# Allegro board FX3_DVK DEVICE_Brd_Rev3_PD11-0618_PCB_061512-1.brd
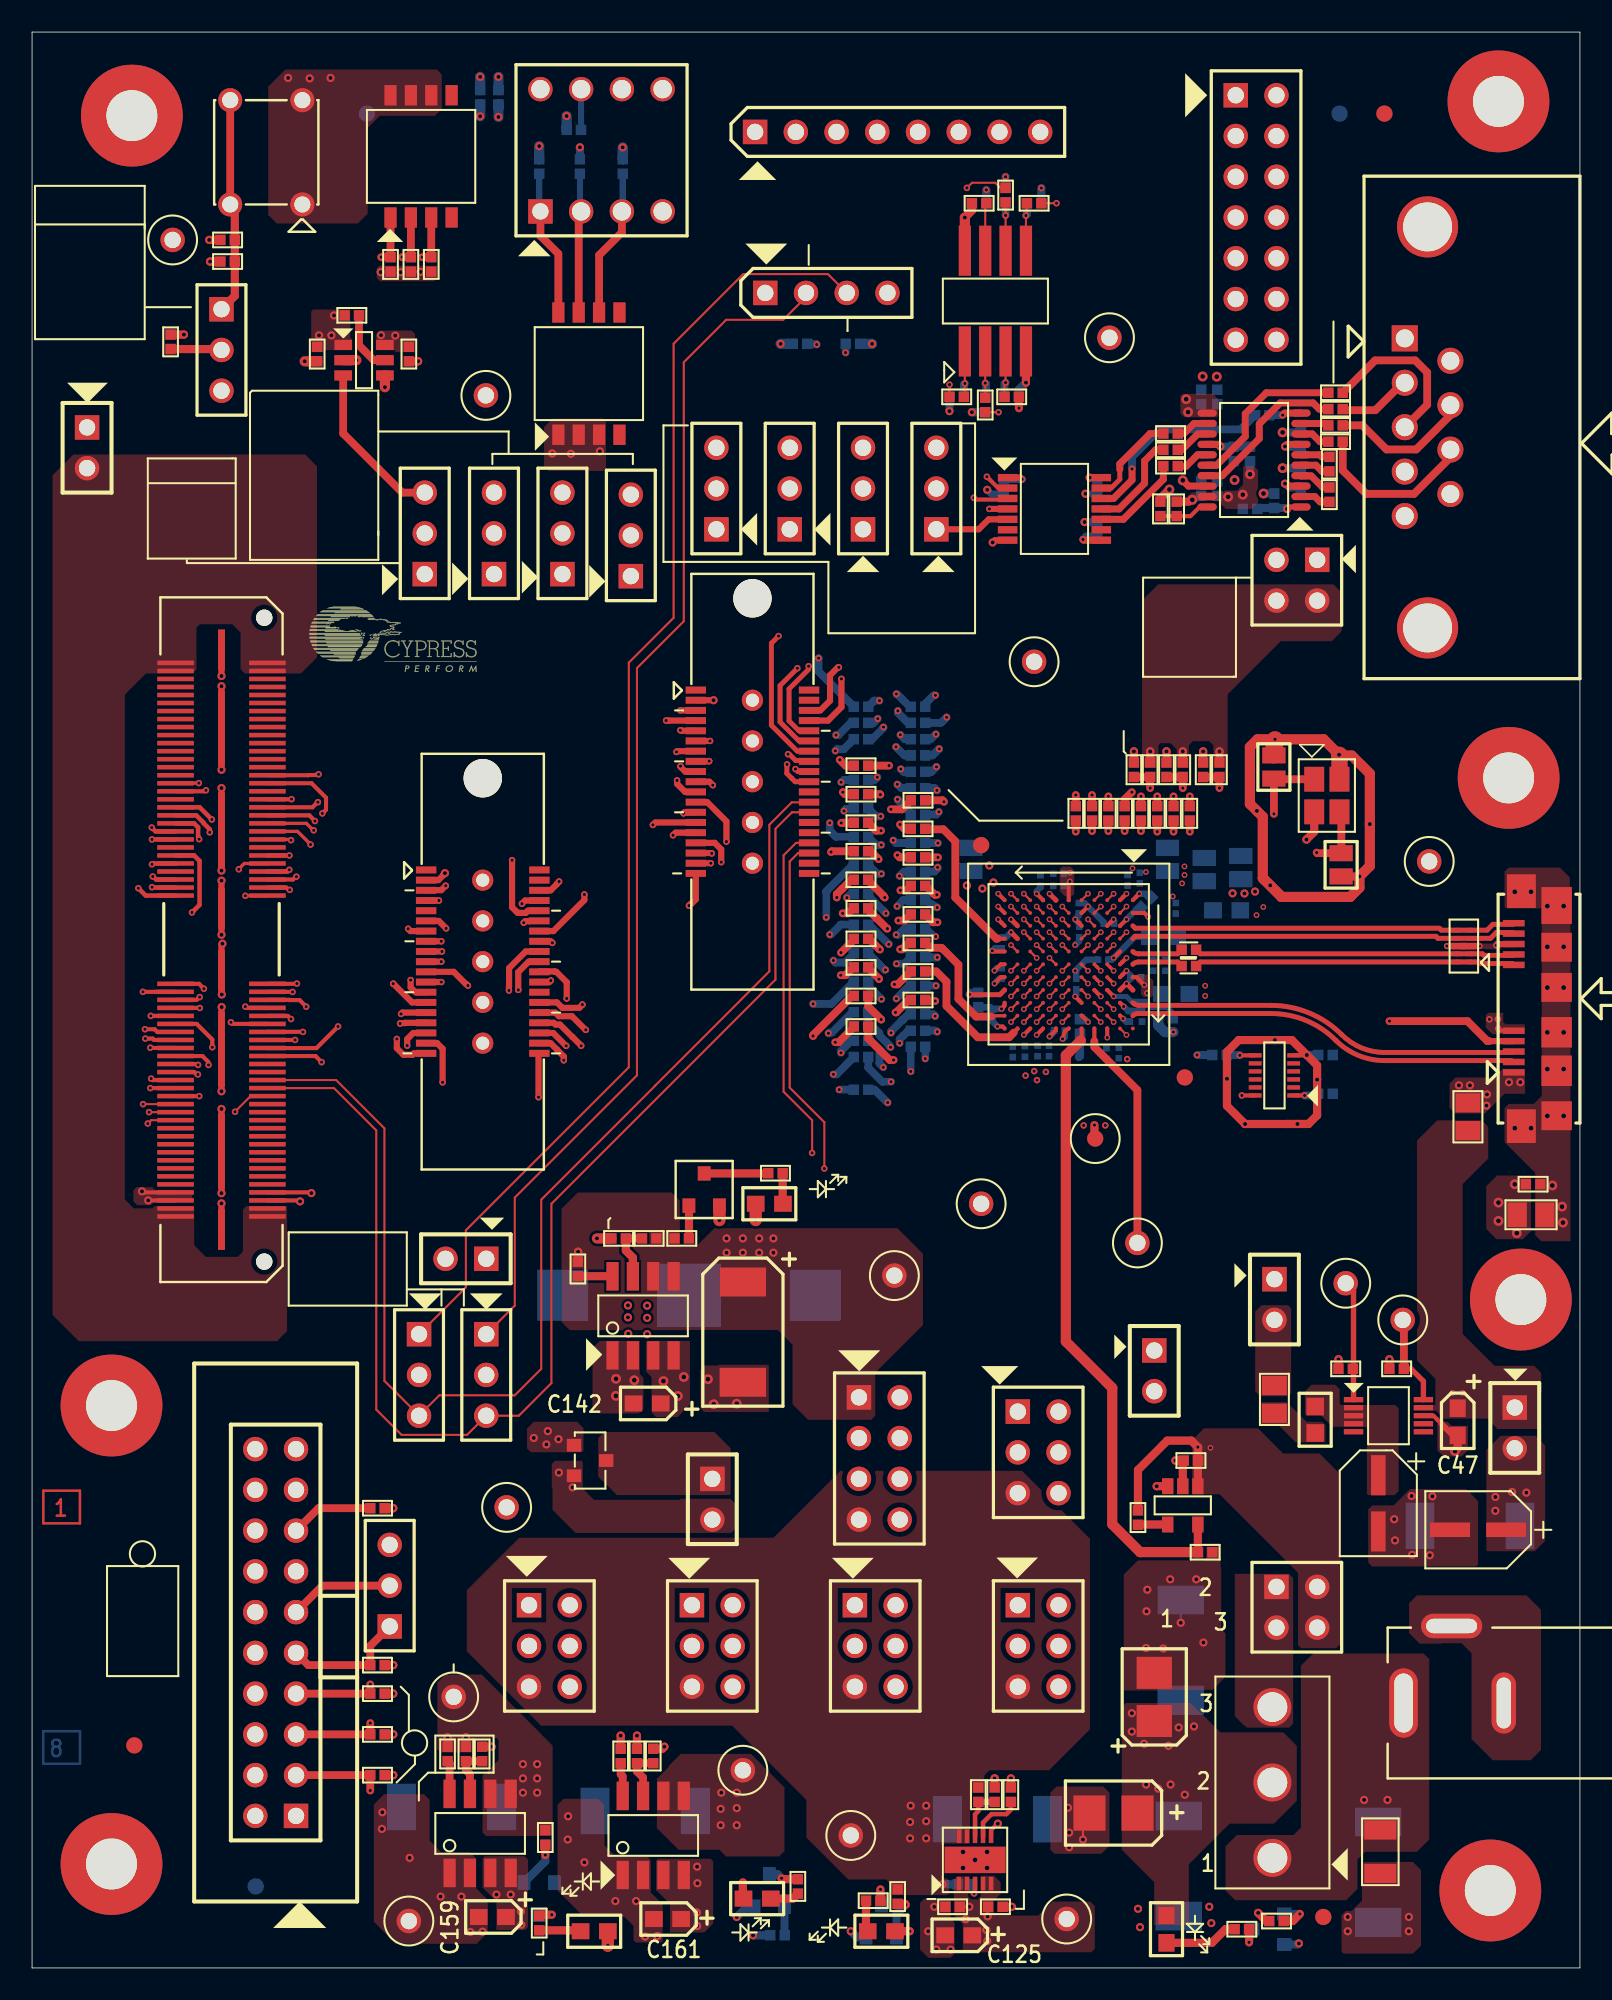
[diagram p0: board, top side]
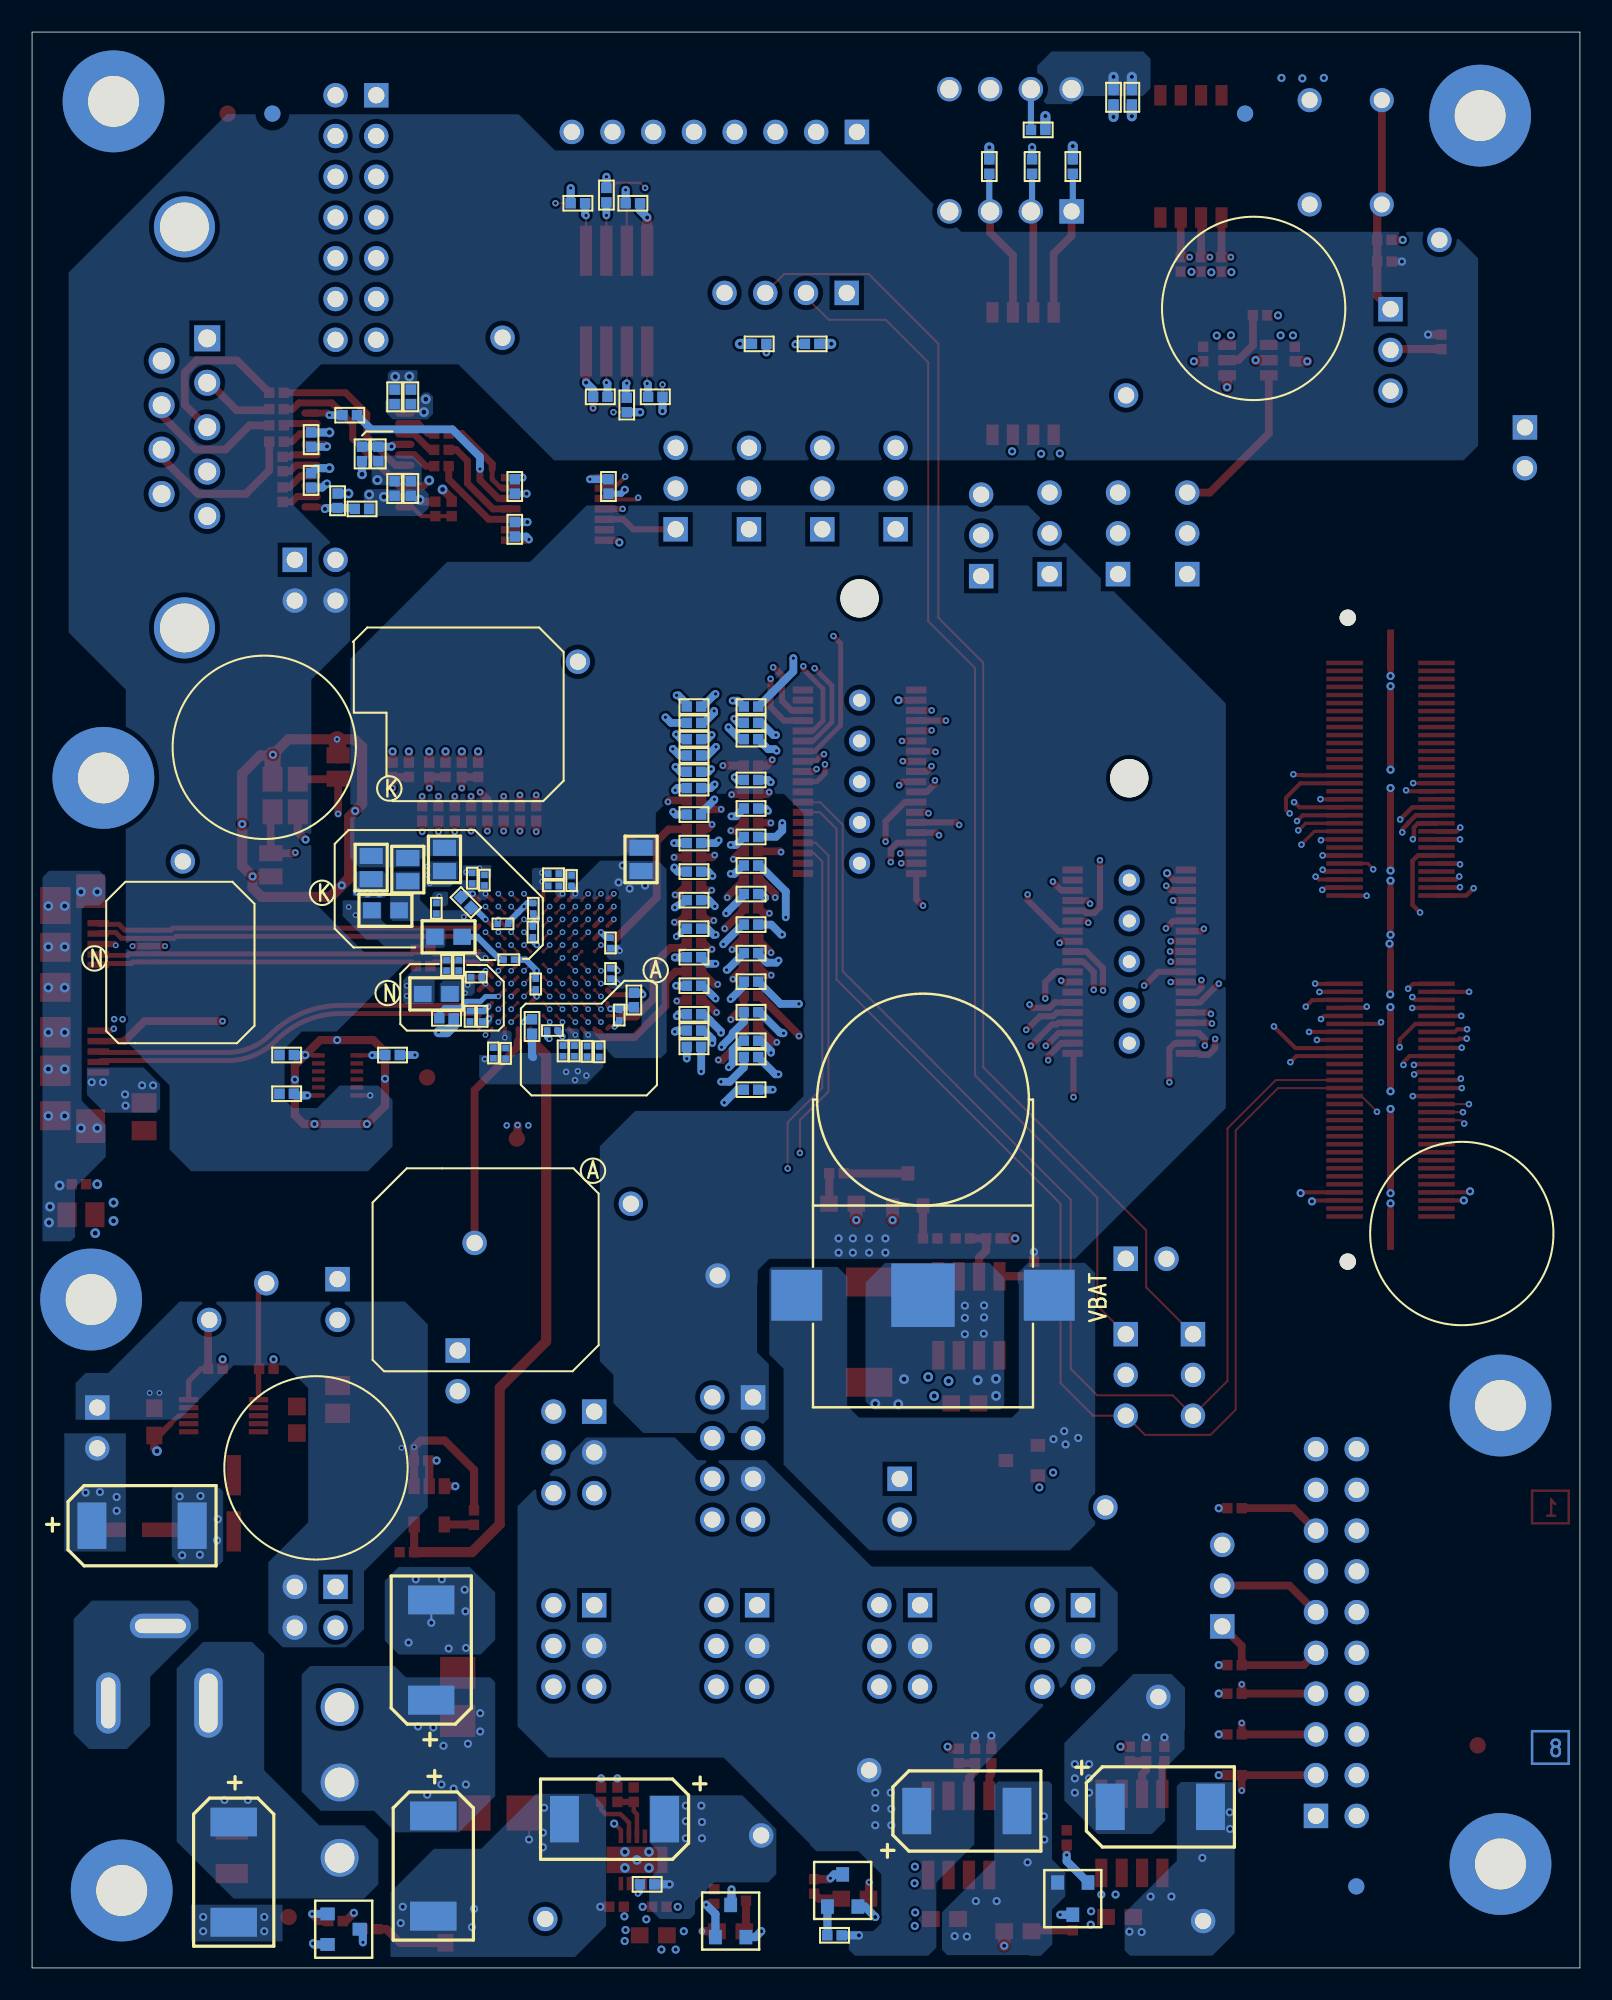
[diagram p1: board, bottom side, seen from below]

Outline 96.52 x 120.65 mm; copper layers: TOP, GND1#2, SIG1#3, PWR1#4, PWR2#5, SIG2#6, GND2#7, BOTTOM. Coordinates in mm from the lower left corner of the outline.
Outline path: 0,120.65 0,0 96.52,0 96.52,120.65 0,120.65

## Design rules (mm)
net group DIFFPAIR0: nets SS_RX_M SS_RX_P
net group DIFFPAIR1: nets N17052408 N17056303
net group DIFFPAIR2: nets SS_DM SS_DP
net group DIFFPAIR3: nets SS_TX_M SS_TX_P
net group USB3.0B: nets OTG_ID USB3_VBUS
net group USBSWITCH: nets FAULTA_L USB_DRV_VBUS
net group EFVDDQ: nets N21905847
net group JTAGI2C: nets N_SRST RTCK TCK TDI TDO TMS TRST_N
net group P-PORT_P-MODE-DEV-TER: nets N20192601 N20198119 N20199051 N20199985
net group P_PORT-DEV-TER: nets N20184217 N20186132 N20187007 N20187884 N20188787 N20188789 N20188799 N20188809 N20189728 N20189730 N20189740 N20189750 N20190677 N20190679 N20190689 N20190699 N20191634 N20191636 N20191646 N20191656 N20192599 N20192611 N20192621 N20193572 N20193574 N20193584 N20193594 N20194553 N20195482
net group P_PORT-PMODE_HDR-SAMTEC: nets CTL4 PMODE0_CON PMODE1_CON PMODE2_CON
net group P_PORT-TER-HDR: nets CTL4_SW PMODE_0 PMODE_1 PMODE_2
net group P_PORT-TER-SAMTEC: nets CTL0 CTL1 CTL2 CTL3 CTL5 CTL6 CTL7 CTL8 CTL9 CTL10 CTL11 CTL12 DQ0 DQ1 DQ2 DQ3 DQ4 DQ5 DQ6 DQ7 DQ8 DQ9 DQ10 DQ11 DQ12 DQ13 DQ14 DQ15 PCLK
net group RESETCONN: nets RESET_N RESET_N_CON RESET_SWITCH
net group S1-TER-DEV: nets N21902708 N21902721 N21902734 N21902747
net group S1-TER-SAMTEC: nets DQ28 DQ29 DQ30 DQ31
net group S1LEVELTRANSLATOR: nets N13841009 UART_CTS_LT UART_RTS_LT UART_RX_LT UART_TX_LT
net group S1UART: nets UART_FORCE_OFF UART_FORCE_ON UART_READY
net group SO-TER-DEV: nets N21902204 N21902237 N21902264 N21902291 N21902318 N21902345 N21902372 N21902399 N21902426 N21902453 N21902480 N21902507
net group SO_PORT-TER-SAMTEC: nets DQ16 DQ17 DQ18 DQ19 DQ20 DQ21 DQ22 DQ23 DQ24 DQ25 DQ26 DQ27
net group SPDTSWITCH: nets SPI_CLK SPI_MISO SPI_MOSI SPI_SSN

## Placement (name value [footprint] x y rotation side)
BT1  SR1130 (3000TR)  [SR1130_3000TR]  40.97 41.93 180 bottom
C1  0.1uF  [C0402]  12.19 107.7 180 top
C2  0.1uF  [C0402]  17.78 100.58 270 top
C3  0.1uF  [C0402]  23.5 100.58 270 top
C28  0.1uF  [C0402]  73.91 92.2 90 bottom
C29  0.01uF  [C0402]  72.9 92.2 90 bottom
C30  0.1uF  [C0402]  73.91 97.92 90 bottom
C31  0.01uF  [C0402]  72.9 97.92 90 bottom
C32  0.1uF  [C0402]  79.12 92.71 90 bottom
C33  0.1uF  [C0402]  80.9 91.82 90 top
C34  0.1uF  [C0402]  79.12 95.25 90 bottom
C35  0.1uF  [C0402]  80.9 93.73 90 top
C36  0.1uF  [C0402]  60.58 92.33 270 bottom
C37  0.1uF  [C0402]  66.42 92.33 270 bottom
C39  0.1uF  [C0402]  80.64 56.9 180 bottom
C42  1uF / 50v  [EEE-1HA010NR]  83.95 28.96 270 top
C43  0.1uF  [C0402]  72.14 63.46 0 top
C44  1uF / 50v  [EEE-1HA010NR]  90.17 27.3 180 top
C45  150uF / 20V  [SIZE_X]  89.66 27.56 180 bottom
C46  0.1uF  [C0402]  72.14 62.44 0 top
C47  4.7uF  [TANT_0603]  88.9 34.04 270 top
C49  0.1uF  [C0402]  93.6 48.84 180 top
C53  100nF  [C0402]  65.34 58.67 270 bottom
C77  0.1uF  [C0402]  59.05 109.98 0 bottom
C78  0.1uF  [C0201]  60.45 61.98 90 bottom
C79  0.1uF  [C0201]  64.07 58.42 180 bottom
C80  0.1uF  [C0201]  62.88 67.77 90 bottom
C81  0.01uF  [C0201]  67.16 65.07 180 bottom
C82  0.01uF  [C0201]  65.11 61.32 90 bottom
C83  0.1uF  [C0201]  61.15 57.1 270 bottom
C84  0.1uF  [C0201]  60.45 63.88 90 bottom
C85  0.01uF  [C0201]  61.91 57.12 270 bottom
C86  0.1uF  [C0201]  62.7 57.15 270 bottom
C87  0.1uF  [C0201]  63.41 57.15 270 bottom
C88  0.01uF  [C0201]  59.91 59.39 270 bottom
C89  0.1uF  [C0201]  66.99 57 270 bottom
C90  0.01uF  [C0201]  67.76 57.02 270 bottom
C91  0.1uF  [C0201]  71.31 66.04 90 bottom
C92  2.2 uF  [C0603]  74.49 65.91 0 bottom
C102  0.1uF  [C0201]  68.82 61.75 180 bottom
C103  2.2 uF  [C0603]  71.31 60.71 0 bottom
C104  0.1uF  [C0201]  66.79 62.84 180 bottom
C105  2.2 uF  [C0603]  70.55 64.26 0 bottom
C106  0.1uF  [C0201]  69.22 59.31 90 bottom
C107  0.01uF  [C0201]  68.45 59.31 90 bottom
C108  0.1uF  [C0201]  64.01 68.2 180 bottom
C109  0.01uF  [C0201]  64.01 67.44 180 bottom
C110  0.1uF  [C0201]  65.29 64.57 270 bottom
C111  0.01uF  [C0201]  65.27 66.04 90 bottom
C112  0.1uF  [C0201]  70.68 62.48 270 bottom
C113  0.01uF  [C0201]  69.91 62.48 270 bottom
C114  0.1uF  [C0201]  69.08 67.92 90 bottom
C115  0.01uF  [C0201]  68.31 67.79 90 bottom
C119  22uF  [SIZE_X]  83.95 5.97 270 bottom
C120  10uF  [C1206]  84.07 7.24 270 top
C121  100uF_10V  [C3528_TAJB107M010RNJ]  69.98 16.89 90 top
C122  100uF_10V  [C3528_TAJB107M010RNJ]  67.44 9.65 180 top
C123  330uF_10V  [C7343_TAJD337K010RNJ]  71.5 6.35 270 bottom
C124  330uF_10V  [C7343_TAJD337K010RNJ]  71.63 19.81 90 bottom
C125  4.7uF  [TANT_0603]  57.78 2.03 180 top
C126  1uF  [C0402]  57.4 3.81 180 top
C127  1uF  [C0402]  60.07 3.81 0 top
C128  10uF_35V  [SIZED]  60.2 9.27 0 bottom
C129  OPEN  [C0402]  61.04 10.79 90 top
C142  4.7uF  [TANT_0603]  38.35 35.18 180 top
C143  10uF_35V  [SIZED]  44.32 39.62 270 top
C158  10uF_35V  [SIZED]  26.16 10.03 180 bottom
C159  4.7uF  [TANT_0603]  28.7 3.17 180 top
C160  10uF_35V  [SIZED]  38.23 9.78 180 bottom
C161  4.7uF  [TANT_0603]  39.62 3.05 180 top
C185  1uF  [C0402]  72.26 31.62 180 top
C186  1uF  [C0402]  73.15 25.91 0 top
C197  0.01uF  [C0402]  29.08 116.59 270 bottom
C212  0.1uF  [C0402]  27.94 116.59 270 bottom
C216  12pF  [C0805]  77.44 74.85 270 top
C217  12pF  [C0805]  81.63 68.75 270 top
D1  BAT54C  [SOT23-BAT54C-7-F]  34.8 31.62 270 top
D14  LED  [LED_0603]  45.97 47.62 0 top
D15  LED  [LED_0603]  52.96 2.29 180 top
D16  LED  [LED_0603]  70.74 2.41 270 top
D17  LED  [LED_0603]  45.21 4.32 0 top
D18  LED  [LED_0603]  35.05 2.29 180 top
F1  FUSE 0.63A  [MFU0603FF00630P100]  80.01 34.16 90 top
FB1  MPZ2012S601A  [FB0805]  58.55 69.09 90 bottom
FB2  MPZ2012S601A  [FB0805]  75.38 68.58 90 bottom
FB4  MPZ2012S601A  [FB0805]  73.09 68.45 90 bottom
FB5  MPZ2012S601A  [FB0805]  70.8 69.09 90 bottom
J1  -  [2-5767004-2]  28.1 62.72 90 top
J2  -  [2-5767004-2]  44.92 73.93 90 top
J20  HDR14_100MIL  [HDR2X7_100MIL]  75.06 116.71 270 top
J34  HDR8_100MIL  [HDR1X8_100MIL]  45.09 114.43 0 top
J38  -  [182-009-213R181]  96.52 96.01 90 top
J40  HEADER2_100mil  [HDR_1X2_100MIL]  77.47 42.93 270 top
J42  HEADER_1x3_100mil  [HEADER_1X3_100MIL]  28.32 39.5 270 top
J45  HEADER_1x3_100mil  [HEADER_1X3_100MIL]  24.13 39.5 270 top
J47  HEADER2_100mil  [HDR_1X2_100MIL]  92.46 34.92 270 top
J48  USB_3  [USB3_CMS1811-010010]  96.52 57.11 90 top
J49  RAPC712X  [RAPC712]  88.52 16.51 90 top
J50  HEADER2_100mil  [HDR_1X2_100MIL]  69.98 38.48 270 top
J51  -  [N2520-6002-RB]  16.46 9.47 90 top
J52  HEADER_1x3_100mil  [HEADER_1X3_100MIL]  22.3 21.29 90 top
J53  HEADER_2x2_100mil  [HEADER_2X2_100MIL]  77.6 23.75 270 top
J72  HEADER_1x3_100mil  [HEADER_1X3_100MIL]  11.81 103.38 270 top
J74  -  [HDR_1X2_100MIL]  42.42 30.48 270 top
J77  QSH_120pin_CONN  [QSH-060-01-L-D-A]  11.81 64.08 270 top
J96  HEADER_1x3_100mil  [HEADER_1X3_100MIL]  28.8 86.87 90 top
J97  HEADER_1x3_100mil  [HEADER_1X3_100MIL]  33.07 86.87 90 top
J98  HEADER_1x3_100mil  [HEADER_1X3_100MIL]  37.34 86.74 90 top
J100  HEADER_1x3_100mil  [HEADER_1X3_100MIL]  24.49 86.87 90 top
J101  HEADER_1x3_100mil  [HEADER_1X3_100MIL]  42.67 89.66 90 top
J102  HEADER_1x3_100mil  [HEADER_1X3_100MIL]  47.24 89.66 90 top
J103  HEADER_1x3_100mil  [HEADER_1X3_100MIL]  51.82 89.66 90 top
J104  HEADER_1x3_100mil  [HEADER_1X3_100MIL]  56.39 89.66 90 top
J125  HEADER_1x2_100mil  [HEADER_1X2_100MIL]  3.43 96.01 270 top
J134  HEADER_4x2_100mil  [HEADER_4X2_100MIL]  51.56 35.56 270 top
J135  HEADER_2x2_100mil  [HEADER_2X2_100MIL]  80.14 87.76 180 top
J136  HEADER_3x2_100mil  [HEADER_3X2_100MIL]  41.15 22.61 270 top
J143  HEADER_3x2_100mil  [HEADER_3X2_100MIL]  61.47 34.67 270 top
J144  HEADER_3x2_100mil  [HEADER_3X2_100MIL]  30.99 22.61 270 top
J145  HEADER_3x2_100mil  [HEADER_3X2_100MIL]  51.31 22.61 270 top
J146  HEADER_3x2_100mil  [HEADER_3X2_100MIL]  61.47 22.61 270 top
J147  HDR_1X4  [HDR_1X4_100MIL]  45.72 104.39 0 top
J156  HEADER_1x2_100mil  [HEADER_1X2_100MIL]  28.32 44.2 180 top
L1  FERRITE BEAD  [BLM21PG221SN1D]  77.47 35.43 270 top
L2  FERRITE BEAD  [BLM21PG221SN1D]  89.53 53.05 270 top
L5  FERRITE BEAD  [BLM21PG221SN1D]  93.47 46.94 180 top
NOREF  -  [unnamed]  91.44 116.33 0 top
NOREF#2  -  [unnamed]  84.33 115.57 0 top
NOREF#3  -  [unnamed]  4.95 35.05 0 top
NOREF#4  -  [unnamed]  92.08 74.17 0 top
NOREF#5  -  [unnamed]  4.95 6.48 0 top
NOREF#6  -  [unnamed]  59.18 69.98 0 top
NOREF#7  -  [unnamed]  92.84 41.66 0 top
NOREF#8  -  [unnamed]  90.93 4.83 0 top
NOREF#9  -  [unnamed]  6.22 115.44 0 top
NOREF#10  -  [unnamed]  6.38 13.87 0 top
NOREF#11  -  [unnamed]  80.52 3.17 0 top
NOREF#12  -  [#2]  0 0 90 top
NOREF#13  -  [unnamed]  71.88 55.5 0 top
NOREF#14  -  [#2]  0 120.65 0 top
NOREF#15  -  [unnamed]  13.94 5.08 180 bottom
NOREF#16  -  [unnamed]  81.53 115.57 180 bottom
NOREF#17  -  [unnamed]  20.88 115.57 180 bottom
Q13  MMBT3904  [SOT23_MMBT]  41.91 48.51 0 top
Q14  MMBT3904  [SOT23_MMBT]  31.62 4.32 0 bottom
Q15  MMBT3904  [SOT23_MMBT]  52.96 2.92 180 bottom
Q16  MMBT3904  [SOT23_MMBT]  77.09 2.41 270 bottom
Q17  MMBT3904  [SOT23_MMBT]  45.97 4.83 180 bottom
R5  22  [R0402]  51.69 56.77 180 bottom
R6  22  [R0402]  55.24 71.88 180 bottom
R7  10K  [R0402]  22.35 106.17 270 top
R8  10K  [R0402]  23.62 106.17 270 top
R10  10K  [R0402]  8.64 101.35 90 top
R11  10K  [R0402]  19.94 103 180 top
R12  22  [R0402]  55.24 70.1 180 bottom
R13  22  [R0402]  55.24 72.77 180 top
R14  22  [R0402]  55.24 74.55 180 bottom
R15  22  [R0402]  51.69 70.48 180 bottom
R16  22  [R0402]  55.24 75.56 180 bottom
R17  22  [R0402]  51.69 72.26 180 bottom
R18  22  [R0402]  51.69 71.37 180 top
R19  10K  [R0402]  24.89 106.17 270 top
R20  22  [R0402]  55.24 77.6 180 bottom
R21  22  [R0402]  51.69 74.04 180 bottom
R22  10K  [R0402]  75.95 90.93 180 bottom
R23  DNL  [R0402]  77.47 91.44 270 bottom
R24  0  [R0402]  70.99 94.61 180 top
R25  0  [R0402]  81.28 97.16 180 top
R26  0  [R0402]  76.71 96.77 180 bottom
R27  0  [R0402]  81.28 96.14 180 top
R28  0  [R0402]  70.99 93.6 180 top
R29  0  [R0402]  81.28 98.17 180 top
R30  10K  [R0402]  75.95 94.36 270 bottom
R31  10K  [R0402]  71.37 90.93 90 top
R32  0  [R0402]  70.99 95.63 180 top
R33  0  [R0402]  81.28 95.12 180 top
R34  DNL  [R0402]  74.93 94.36 90 bottom
R35  DNL  [R0402]  70.36 90.93 270 top
R36  10K  [R0402]  66.42 89.66 90 bottom
R37  10K  [R0402]  69.72 74.68 90 top
R38  10K  [R0402]  71.75 74.68 90 top
R39  10K  [R0402]  74.04 74.68 90 top
R40  0  [R0402]  80.64 54.48 180 bottom
R41  10K  [R0402]  68.71 74.68 270 top
R42  10K  [R0402]  70.74 74.68 270 top
R43  33  [R0402]  74.04 56.9 0 bottom
R44  22  [R0402]  55.24 76.58 180 bottom
R45  22  [R0402]  55.24 78.61 180 bottom
R46  100K  [R0402]  85.09 37.34 0 top
R47  200 / 1%  [R0402]  69.47 66.4 45 bottom
R48  6.04K / 1%  [R0402]  70.68 59.18 180 bottom
R49  22  [R0402]  55.24 73.53 180 bottom
R50  22  [R0402]  51.69 77.6 180 bottom
R51  10K  [R0402]  21.54 28.65 0 top
R52  10K  [R0402]  21.54 18.87 0 top
R53  10K  [R0402]  21.54 17.09 0 top
R54  10K  [R0402]  21.54 14.55 0 top
R55  10K  [R0402]  21.54 12.01 0 top
R56  22  [R0402]  51.69 78.61 180 bottom
R57  22  [R0402]  51.69 76.58 180 bottom
R58  10K  [R0402]  73.03 74.68 270 top
R59  0  [R0402]  62.48 109.98 180 top
R60  0  [R0402]  59.44 97.41 90 top
R61  0  [R0402]  60.71 110.49 270 top
R62  0  [R0402]  57.66 97.92 0 top
R63  100K  [R0402]  12.19 106.35 180 top
R110  10K  [R0402]  36.83 112.27 270 bottom
R111  0  [R0402]  33.78 114.55 180 bottom
R139  10K  [R0402]  34.04 43.56 90 top
R141  430  [R0402]  38.48 45.47 0 top
R144  30.1K  [R0402]  36.58 45.47 0 top
R170  DNL  [R0402]  58.99 60.33 270 bottom
R176  2K  [R0402]  47.88 101.22 180 bottom
R186  2K  [R0402]  51.18 101.22 0 bottom
R190  1M  [R0402]  68.96 28.07 90 top
R205  22  [R0402]  51.69 57.78 180 bottom
R206  22  [R0402]  55.24 60.33 180 top
R207  22  [R0402]  55.24 57.4 180 bottom
R208  22  [R0402]  51.69 58.67 180 top
R209  22  [R0402]  51.69 66.93 180 bottom
R210  22  [R0402]  55.24 58.42 180 bottom
R211  22  [R0402]  51.69 62.36 180 top
R212  22  [R0402]  55.24 59.44 180 bottom
R213  22  [R0402]  51.69 59.56 180 bottom
R214  22  [R0402]  55.24 62.1 180 top
R215  22  [R0402]  55.24 63.88 180 top
R216  22  [R0402]  51.69 60.58 180 top
R217  22  [R0402]  51.69 61.47 180 bottom
R218  22  [R0402]  55.24 62.99 180 bottom
R219  22  [R0402]  55.24 61.21 180 bottom
R220  22  [R0402]  55.24 66.55 180 bottom
R221  22  [R0402]  55.24 64.77 180 bottom
R222  22  [R0402]  51.69 64.14 180 top
R223  22  [R0402]  51.69 65.02 180 bottom
R224  22  [R0402]  55.24 69.22 180 top
R225  22  [R0402]  55.24 65.66 180 top
R226  22  [R0402]  51.69 69.6 180 top
R227  22  [R0402]  51.69 66.04 180 top
R228  22  [R0402]  51.69 63.25 180 bottom
R229  22  [R0402]  51.69 54.74 180 bottom
R230  22  [R0402]  55.24 67.44 180 top
R231  22  [R0402]  51.69 67.82 180 top
R232  22  [R0402]  55.24 68.33 180 bottom
R233  22  [R0402]  51.69 68.71 180 bottom
R234  22  [R0402]  51.69 74.93 180 top
R235  22  [R0402]  51.69 73.15 180 top
R236  22  [R0402]  55.24 70.99 180 top
R237  1K  [R0402]  58.17 5.21 180 bottom
R238  1.15K  [R0402]  60.02 10.79 270 top
R239  3.57K  [R0402]  59 10.79 90 top
R240  30.1K  [R0402]  28.07 13.34 270 top
R241  10K  [R0402]  25.91 13.34 90 top
R242  15.8K  [R0402]  27.05 13.34 270 top
R243  30.1K  [R0402]  38.73 13.21 270 top
R244  10K  [R0402]  36.7 13.21 90 top
R245  33.2K  [R0402]  37.72 13.21 270 top
R246  100K  [R0402]  59.44 97.41 90 bottom
R247  100K  [R0402]  60.71 110.49 270 bottom
R248  4.7K  [R0402]  59.05 109.98 0 top
R249  4.7K  [R0402]  57.66 97.92 0 bottom
R250  4.7K  [R0402]  61.09 97.92 180 top
R251  DNP  [R0402]  61.09 97.92 180 bottom
R252  100K  [R0402]  62.48 109.98 180 bottom
R254  22  [R0402]  67.11 71.96 90 top
R255  22  [R0402]  68.13 71.96 90 top
R256  22  [R0402]  65.08 71.96 90 top
R257  22  [R0402]  66.1 71.96 90 top
R258  22  [R0402]  69.15 71.96 90 top
R259  22  [R0402]  70.16 71.96 90 top
R260  22  [R0402]  71.18 71.96 90 top
R261  22  [R0402]  72.19 71.96 90 top
R262  10K  [R0402]  31.62 112.27 270 bottom
R263  10K  [R0402]  34.16 112.27 270 bottom
R264  10K  [R0402]  81.92 37.34 180 top
R300  1K  [R0402]  40.51 45.47 0 top
R301  180  [R0402]  46.35 49.53 0 top
R302  180  [R0402]  31.62 2.79 270 top
R306  1K  [R0402]  32 8.13 270 top
R307  180  [R0402]  52.45 4.19 180 top
R308  1K  [R0402]  53.98 4.45 270 top
R309  180  [R0402]  75.44 2.41 180 top
R310  1K  [R0402]  77.6 2.92 0 top
R311  180  [R0402]  47.75 5.08 270 top
R312  1K  [R0402]  46.48 2.03 0 bottom
SW8  PBSwitch  [PUSHBUTTON_EVQ]  14.61 113.16 180 top
SW9  SPDT_SWITCH  [SPDT_POWER_SWITCH]  77.34 11.56 90 top
SW25  DIP_SWITCH_4POS  [SPST4_DIP_218-4LPST]  24.26 112.9 90 top
SW40  DIP_SWITCH_4POS  [SPST4_DIP_218-4LPST]  34.72 99.36 90 top
TP9  TP_LOOP_RED  [TP_RED_5000]  64.52 3.05 90 top
TP10  TP_LOOP_RED  [TP_RED_5000]  51.05 8.26 0 top
TP11  TP_LOOP_BLACK  [TP_BLACK_5001]  23.5 2.92 0 top
TP12  TP_LOOP_BLACK  [TP_BLACK_5001]  8.76 107.7 0 top
TP13  TP_4060  [TEST_POINT_40-60]  28.3 98.01 90 top
TP14  TP_LOOP_BLACK  [TP_BLACK_5001]  67.18 101.6 0 top
TP15  TP40_SMD  [TP_SMD]  66.29 51.69 0 top
TP16  TP_LOOP_BLACK  [TP_BLACK_5001]  29.59 28.7 0 top
TP17  TP_LOOP_BLACK  [TP_BLACK_5001]  87.12 68.96 0 top
TP18  TP_LOOP_BLACK  [TP_BLACK_5001]  59.18 47.62 0 top
TP19  TP_LOOP_BLACK  [TP_BLACK_5001]  62.48 81.41 0 top
TP28  TP_4060  [TEST_POINT_40-60]  85.47 40.39 0 top
TP31  TP_4060  [TEST_POINT_40-60]  68.93 45.18 180 top
TP43  TP_LOOP_RED  [TP_RED_5000]  53.77 43.15 90 top
TP44  TP_LOOP_RED  [TP_RED_5000]  26.29 16.89 90 top
TP45  TP_LOOP_RED  [TP_RED_5000]  44.32 12.32 270 top
TP46  TP_4060  [TEST_POINT_40-60]  81.92 42.67 0 top
U1  -  [FX3_121_BUMP]  64.64 62.55 270 top
U6  MAX13235EEUP+  [MAX13235_TSSOP20]  76.2 93.98 180 top
U7  MAX3378  [TSSOP14]  63.75 90.93 0 top
U8  -  [MAX1823BEUB]  84.58 34.42 0 top
U9  ESD Protector  [UDFN10_SP3010]  89.28 63.69 90 top
U17  -  [TPS74801DRCR]  58.8 6.73 90 top
U19  TPS76801QD  [SOIC8_TPS76801QD]  38.1 40.64 90 top
U20  TPS76801QD  [SOIC8_TPS76801QD]  27.94 8.38 90 top
U23  TPS76801QD  [SOIC8_TPS76801QD]  38.73 8.26 90 top
U26  M25P40-VMN6TPB  [M25P40-VMN6TPB_SO8]  60.07 103.89 90 top
U37  NCP361SNT1G  [NCP361SNT1G_TSOP5]  71.75 28.83 270 top
U44  -  [110-44-308-41-001000]  35.51 113.28 90 top
U45  BI_LVL_TRANS_1BIT  [SOT23_6_TXS0101]  20.7 100.2 0 top
X2  OSCILLATOR - 32.768KHz  [SG_3040LC]  77.47 55.63 180 top
Y3  CRYSTAL  [XTAL_ITTI]  80.74 73.07 180 top

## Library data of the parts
BT1 = Battery_3000
C1-C3 C120 = CAPACITOR NON-POL
C28-C37 C39 C43 C46 C49 C53 C77-C92 C102-C115 C197 C212 = Cap
C42 C44 C45 C47 C126 C127 C129 C185 C186 = CAP
C119 = C_0
C121-C124 C128 C143 C158 C160 = CAP_POL
C125 C142 C159 C161 = PCAP
C216 C217 = 12 pFd 0805_1
D1 = BAT54C
D14-D18 = LED
F1 = FUSE
FB1 FB2 FB4 FB5 L1 L2 L5 = INDUCTOR
J1 J2 = MICTOR HEADER_1
J20 = HEADER_2X7
J34 = HEADER_8
J38 = DSUB_0
J40 J47 J50 J74 = HEADER2_100mil
J42 J45 J52 J72 J96-J98 J100-J104 = HEADER_1x3_100mil
J48 = GSB343133HR_2
J49 = CONN_JACK_PWR: Tolerance: TOL
J51 = 2520-6002UB
J53 = HEADER_2x2_100mil
J77 = QTH120_CONN
J125 J156 = HEADER2
J134 = PWR_HDR8
J135 = PWR_HDR4
J136 J143-J146 = PWR_HDR6
J147 = HDR_1X4
Q13-Q17 = NPN ECB_0
R5-R8 R12-R42 R44-R58 R63 R139 R141 R144 R170 R176 R186 R190 R205-R252 R254-R261 R300 R306 R308 R310 R312 = R
R10 R11 R43 R59-R62 R110 R111 R262-R264 R301 R302 R307 R309 R311 = RESISTOR
SW8 = EVQPAC07K_0
SW9 = SPDT_SWITCH_0
SW25 SW40 = DIP_SWITCH4
TP9-TP12 TP14 TP16-TP19 TP43-TP45 = TP_LOOP_RED
TP13 TP28 TP31 TP46 = T POINT A
TP15 = TESTPOINT
U1 = FX3_121_BUMP_5
U6 = MAX13235EEUP_0
U7 = MAX3378_0
U8 = MAX1823BEUB
U9 = AZ1065-06Q_0
U17 = TPS74801DRCR_0
U19 U20 U23 = TPS76801QD
U26 = M25P32-VMW6G
U37 = NCP361SNT1G_0
U44 = 24LC256
U45 = BI_LVL_TRANS_1BIT
X2 = OSCILLATOR_2
Y3 = CRYSTAL_1

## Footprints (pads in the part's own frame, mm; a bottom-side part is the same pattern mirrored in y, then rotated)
2-5767004-2
  round 2.388 hole 2.388 unplated: (11.43,0)
  rect 0.432x1.27 smd: 1(5.715,3.531) 2(5.715,-3.531) 3(5.08,3.531) 4(5.08,-3.531) 5(4.445,3.531) 6(4.445,-3.531) 7(3.81,3.531) 8(3.81,-3.531) 9(3.175,3.531) 10(3.175,-3.531) 11(2.54,3.531) 12(2.54,-3.531) 13(1.905,3.531) 14(1.905,-3.531) 15(1.27,3.531) 16(1.27,-3.531) 17(0.635,3.531) 18(0.635,-3.531) 19(0,3.531) 20(0,-3.531) 21(-0.635,3.531) 22(-0.635,-3.531) 23(-1.27,3.531) 24(-1.27,-3.531) 25(-1.905,3.531) 26(-1.905,-3.531) 27(-2.54,3.531) 28(-2.54,-3.531) 29(-3.175,3.531) 30(-3.175,-3.531) 31(-3.81,3.531) 32(-3.81,-3.531) 33(-4.445,3.531) 34(-4.445,-3.531) 35(-5.08,3.531) 36(-5.08,-3.531) 37(-5.715,3.531) 38(-5.715,-3.531)
  round 1.321 hole 0.813: 39(5.08,0) 40(2.54,0) 41(0,0) 42(-2.54,0) 43(-5.08,0)
110-44-308-41-001000
  rect 1.524x1.524 hole 1.016: 1(-3.81,3.81)
  round 1.524 hole 1.143: 2(-3.81,1.27) 3(-3.81,-1.27) 4(-3.81,-3.81) 5(3.81,-3.81) 6(3.81,-1.27) 7(3.81,1.27) 8(3.81,3.81)
182-009-213R181
  rect 1.626x1.626 hole 1.118: 1(5.55,10.922)
  round 1.626 hole 1.118: 2(2.781,10.922) 3(0.013,10.922) 4(-2.756,10.922) 5(-5.524,10.922) 6(4.153,8.077) 7(1.384,8.077) 8(-1.384,8.077) 9(-4.153,8.077)
  round 3.81 hole 3.048: 10(-12.497,9.5) 11(12.497,9.5)
BLM21PG221SN1D
  rect 1.2x1.55 smd: 1(-0.865,0) 2(0.865,0)
C0201
  rect 0.41x0.41 smd: 1(-0.33,0) 2(0.33,0)
C0402
  rect 0.65x0.65 smd: 1(-0.451,0) 2(0.451,0)
C0603
  rect 1.1x1 smd: 1(-0.85,0) 2(0.85,0)
C0805
  rect 1x1.45 smd: 1(-0.725,0) 2(0.725,0)
C1206
  rect 1.2x2 smd: 1(-1.354,0) 2(1.354,0)
C3528_TAJB107M010RNJ
  rect 2x2.2 smd: 1(-1.5,0) 2(1.5,0)
C7343_TAJD337K010RNJ
  rect 1.803x2.896 smd: 1(-3.124,0) 2(3.124,0)
EEE-1HA010NR
  rect 2.504x0.904 smd: 1(-1.752,0) 2(1.752,0)
FB0805
  rect 1x1.45 smd: 1(-0.725,0) 2(0.725,0)
FX3_121_BUMP
  round 0.24 smd: A1(-3.999,3.999) A2(-3.199,3.999) A3(-2.4,3.999) A4(-1.6,3.999) A5(-0.8,3.999) A6(0,3.999) A7(0.8,3.999) A8(1.6,3.999) A9(2.4,3.999) A10(3.199,3.999) A11(3.999,3.999) B1(-3.999,3.199) B2(-3.199,3.199) B3(-2.4,3.199) B4(-1.6,3.199) B5(-0.8,3.199) B6(0,3.199) B7(0.8,3.199) B8(1.6,3.199) B9(2.4,3.199) B10(3.199,3.199) B11(3.999,3.199) C1(-3.999,2.4) C2(-3.199,2.4) C3(-2.4,2.4) C4(-1.6,2.4) C5(-0.8,2.4) C6(0,2.4) C7(0.8,2.4) C8(1.6,2.4) C9(2.4,2.4) C10(3.199,2.4) C11(3.999,2.4) D1(-3.999,1.6) D2(-3.199,1.6) D3(-2.4,1.6) D4(-1.6,1.6) D5(-0.8,1.6) D6(0,1.6) D7(0.8,1.6) D8(1.6,1.6) D9(2.4,1.6) D10(3.199,1.6) D11(3.999,1.6) E1(-3.999,0.8) E2(-3.199,0.8) E3(-2.4,0.8) E4(-1.6,0.8) E5(-0.8,0.8) E6(0,0.8) E7(0.8,0.8) E8(1.6,0.8) E9(2.4,0.8) E10(3.199,0.8) E11(3.999,0.8) F1(-3.999,0) F2(-3.199,0) F3(-2.4,0) F4(-1.6,0) F5(-0.8,0) F6(0,0) F7(0.8,0) F8(1.6,0) F9(2.4,0) F10(3.199,0) F11(3.999,0) G1(-3.999,-0.8) G2(-3.199,-0.8) G3(-2.4,-0.8) G4(-1.6,-0.8) G5(-0.8,-0.8) G6(0,-0.8) G7(0.8,-0.8) G8(1.6,-0.8) G9(2.4,-0.8) G10(3.199,-0.8) G11(3.999,-0.8) H1(-3.999,-1.6) H2(-3.199,-1.6) H3(-2.4,-1.6) H4(-1.6,-1.6) H5(-0.8,-1.6) H6(0,-1.6) H7(0.8,-1.6) H8(1.6,-1.6) H9(2.4,-1.6) H10(3.199,-1.6) H11(3.999,-1.6) J1(-3.999,-2.4) J2(-3.199,-2.4) J3(-2.4,-2.4) J4(-1.6,-2.4) J5(-0.8,-2.4) J6(0,-2.4) J7(0.8,-2.4) J8(1.6,-2.4) J9(2.4,-2.4) J10(3.199,-2.4) J11(3.999,-2.4) K1(-3.999,-3.199) K2(-3.199,-3.199) K3(-2.4,-3.199) K4(-1.6,-3.199) K5(-0.8,-3.199) K6(0,-3.199) K7(0.8,-3.199) K8(1.6,-3.199) K9(2.4,-3.199) K10(3.199,-3.199) K11(3.999,-3.199) L1(-3.999,-3.999) L2(-3.199,-3.999) L3(-2.4,-3.999) L4(-1.6,-3.999) L5(-0.8,-3.999) L6(0,-3.999) L7(0.8,-3.999) L8(1.6,-3.999) L9(2.4,-3.999) L10(3.199,-3.999) L11(3.999,-3.999)
HDR1X8_100MIL
  rect 1.524x1.524 hole 1.016: 1(0,0)
  round 1.524 hole 1.016: 2(2.54,0) 3(5.08,0) 4(7.62,0) 5(10.16,0) 6(12.7,0) 7(15.24,0) 8(17.78,0)
HDR2X7_100MIL
  rect 1.524x1.524 hole 1.016: 1(0,0)
  round 1.524 hole 1.016: 2(2.54,0) 3(5.08,0) 4(7.62,0) 5(10.16,0) 6(12.7,0) 7(15.24,0) 8(15.24,2.54) 9(12.7,2.54) 10(10.16,2.54) 11(7.62,2.54) 12(5.08,2.54) 13(2.54,2.54) 14(0,2.54)
HDR_1X2_100MIL
  rect 1.524x1.524 hole 1.016: 1(0,0)
  round 1.524 hole 1.016: 2(2.54,0)
HDR_1X4_100MIL
  rect 1.524x1.524 hole 1.016: 1(0,0)
  round 1.524 hole 1.016: 2(2.54,0) 3(5.08,0) 4(7.62,0)
HEADER_1X2_100MIL
  rect 1.524x1.524 hole 1.016: 1(0,0)
  round 1.524 hole 1.016: 2(2.54,0)
HEADER_1X3_100MIL
  rect 1.524x1.524 hole 1.016: 1(0,0)
  round 1.524 hole 1.016: 2(2.54,0) 3(5.08,0)
HEADER_2X2_100MIL
  rect 1.524x1.524 hole 1.016: 1(0,0)
  round 1.524 hole 1.016: 2(2.54,0) 3(0,2.54) 4(2.54,2.54)
HEADER_3X2_100MIL
  rect 1.524x1.524 hole 1.016: 1(0,0)
  round 1.524 hole 1.016: 2(2.54,0) 3(5.08,0) 4(5.08,2.54) 5(2.54,2.54) 6(0,2.54)
HEADER_4X2_100MIL
  rect 1.524x1.524 hole 1.016: 1(0,0)
  round 1.524 hole 1.016: 2(2.54,0) 3(5.08,0) 4(7.62,0) 5(7.62,2.54) 6(5.08,2.54) 7(2.54,2.54) 8(0,2.54)
LED_0603
  rect 1.1x1 smd: 1(-0.85,0) 2(0.85,0)
M25P40-VMN6TPB_SO8
  rect 3.124x0.762 smd: 1(-3.137,1.905) 2(-3.137,0.635) 3(-3.137,-0.635) 4(-3.137,-1.905) 5(3.137,-1.905) 6(3.137,-0.635) 7(3.137,0.635) 8(3.137,1.905)
MAX1823BEUB
  rect 1.206x0.333 smd: 1(-2.178,1) 2(-2.178,0.5) 3(-2.178,0) 4(-2.178,-0.5) 5(-2.178,-1) 6(2.178,-1) 7(2.178,-0.5) 8(2.178,0) 9(2.178,0.5) 10(2.178,1)
MAX13235_TSSOP20
  oval 1.208x0.454 smd: 1(-2.925,2.925) 2(-2.925,2.275) 3(-2.925,1.625) 4(-2.925,0.975) 5(-2.925,0.325) 6(-2.925,-0.325) 7(-2.925,-0.975) 8(-2.925,-1.625) 9(-2.925,-2.275) 10(-2.925,-2.925) 11(2.925,-2.925) 12(2.925,-2.275) 13(2.925,-1.625) 14(2.925,-0.975) 15(2.925,-0.325) 16(2.925,0.325) 17(2.925,0.975) 18(2.925,1.625) 19(2.925,2.275) 20(2.925,2.925)
MFU0603FF00630P100
  rect 1.1x1.1 smd: 1(-0.825,0) 2(0.825,0)
N2520-6002-RB
  rect 1.524x1.524 hole 1.016: 1(0,0)
  round 1.524 hole 1.016: 2(0,2.54) 3(2.54,0) 4(2.54,2.54) 5(5.08,0) 6(5.08,2.54) 7(7.62,0) 8(7.62,2.54) 9(10.16,0) 10(10.16,2.54) 11(12.7,0) 12(12.7,2.54) 13(15.24,0) 14(15.24,2.54) 15(17.78,0) 16(17.78,2.54) 17(20.32,0) 18(20.32,2.54) 19(22.86,0) 20(22.86,2.54)
NCP361SNT1G_TSOP5
  rect 0.991x0.711 smd: 1(-1.194,0.94) 2(-1.194,0) 3(-1.194,-0.94) 4(1.194,-0.94) 5(1.194,0.94)
PUSHBUTTON_EVQ
  round 1.5 hole 1: A1(-2.25,3.25) A2(-2.25,-3.25) B1(2.25,3.25) B2(2.25,-3.25)
QSH-060-01-L-D-A
  round 1.016 hole 1.016 unplated: (-20.065,2.667) (20.065,2.667)
  rect 0.28x2.28 smd: 1(-17.25,-2.864) 2(-17.25,2.864) 3(-16.75,-2.864) 4(-16.75,2.864) 5(-16.25,-2.864) 6(-16.25,2.864) 7(-15.75,-2.864) 8(-15.75,2.864) 9(-15.25,-2.864) 10(-15.25,2.864) 11(-14.75,-2.864) 12(-14.75,2.864) 13(-14.25,-2.864) 14(-14.25,2.864) 15(-13.75,-2.865) 16(-13.75,2.864) 17(-13.25,-2.864) 18(-13.25,2.864) 19(-12.75,-2.864) 20(-12.75,2.864) 21(-12.25,-2.864) 22(-12.25,2.864) 23(-11.75,-2.864) 24(-11.75,2.864) 25(-11.25,-2.864) 26(-11.25,2.864) 27(-10.75,-2.864) 28(-10.75,2.864) 29(-10.25,-2.864) 30(-10.25,2.864) 31(-9.75,-2.864) 32(-9.75,2.864) 33(-9.25,-2.864) 34(-9.25,2.864) 35(-8.75,-2.864) 36(-8.75,2.864) 37(-8.25,-2.864) 38(-8.25,2.864) 39(-7.75,-2.864) 40(-7.75,2.864) 41(-7.25,-2.864) 42(-7.25,2.864) 43(-6.75,-2.864) 44(-6.75,2.864) 45(-6.25,-2.864) 46(-6.25,2.864) 47(-5.75,-2.864) 48(-5.75,2.864) 49(-5.25,-2.864) 50(-5.25,2.864) 51(-4.75,-2.864) 52(-4.75,2.864) 53(-4.25,-2.864) 54(-4.25,2.864) 55(-3.75,-2.864) 56(-3.75,2.864) 57(-3.25,-2.864) 58(-3.25,2.864) 59(-2.75,-2.864) 60(-2.75,2.864) 61(2.75,-2.864) 62(2.75,2.864) 63(3.25,-2.864) 64(3.25,2.864) 65(3.75,-2.864) 66(3.75,2.864) 67(4.25,-2.864) 68(4.25,2.864) 69(4.75,-2.864) 70(4.75,2.864) 71(5.25,-2.864) 72(5.25,2.864) 73(5.75,-2.864) 74(5.75,2.864) 75(6.25,-2.864) 76(6.25,2.864) 77(6.75,-2.864) 78(6.75,2.864) 79(7.25,-2.864) 80(7.25,2.864) 81(7.75,-2.864) 82(7.75,2.864) 83(8.25,-2.864) 84(8.25,2.864) 85(8.75,-2.864) 86(8.75,2.864) 87(9.25,-2.864) 88(9.25,2.864) 89(9.75,-2.864) 90(9.75,2.864) 91(10.25,-2.864) 92(10.25,2.864) 93(10.75,-2.864) 94(10.75,2.864) 95(11.25,-2.864) 96(11.25,2.864) 97(11.75,-2.864) 98(11.75,2.864) 99(12.25,-2.864) 100(12.25,2.864) 101(12.75,-2.864) 102(12.75,2.864) 103(13.25,-2.864) 104(13.25,2.864) 105(13.75,-2.864) 106(13.75,2.864) 107(14.25,-2.864) 108(14.25,2.864) 109(14.75,-2.864) 110(14.75,2.864) 111(15.25,-2.864) 112(15.25,2.864) 113(15.75,-2.864) 114(15.75,2.864) 115(16.25,-2.864) 116(16.25,2.864) 117(16.75,-2.864) 118(16.75,2.864) 119(17.25,-2.864) 120(17.25,2.864)
  rect 2.54x0.43 smd: 121(-18.064,0) 124(-1.935,0) 125(1.935,0) 128(18.064,0)
  rect 4.7x0.43 smd: 122(-13.175,0) 123(-6.825,0) 126(6.825,0) 127(13.175,0)
R0402
  rect 0.65x0.65 smd: 1(-0.451,0) 2(0.451,0)
RAPC712
  oval 1.524x3.81 hole 0.889x3.175: 1(4.801,0)
  oval 4.318x1.778 hole 3.683x1.143: 2(0,2.997)
  oval 3.81x1.524 hole 3.175x0.889: 3(0,-3.251)
SG_3040LC
  rect 0.8x0.27 smd: 1(-1.2,1.25) 2(-1.2,0.75) 3(-1.2,0.25) 4(-1.2,-0.25) 5(-1.2,-0.75) 6(-1.2,-1.25) 7(1.2,-1.25) 8(1.2,-0.75) 9(1.2,-0.25) 10(1.2,0.25) 11(1.2,0.75) 12(1.2,1.25)
SIZE_X
  rect 1.803x2.896 smd: 1(-3.124,0) 2(3.124,0)
SIZED
  rect 1.803x2.896 smd: 1(-3.124,0) 2(3.124,0)
SOIC8_TPS76801QD
  rect 1.778x0.762 smd: 1(-2.464,1.905) 2(-2.464,0.635) 3(-2.464,-0.635) 4(-2.464,-1.905) 5(2.464,-1.905) 6(2.464,-0.635) 7(2.464,0.635) 8(2.464,1.905)
SOT23-BAT54C-7-F
  rect 0.8x0.9 smd: 1(0.95,-1) 2(-0.95,-1) 3(0,1)
SOT23_6_TXS0101
  rect 1.1x0.637 smd: 1(-1.3,0.95) 2(-1.3,0) 3(-1.3,-0.95) 4(1.3,-0.95) 5(1.3,0) 6(1.3,0.95)
SOT23_MMBT
  rect 0.8x0.899 smd: 1(-0.95,-1.003) 2(0.95,-1.003) 3(0,1.003)
SPDT_POWER_SWITCH
  round 2.362 hole 1.854: 1(-4.699,0) 2(0,0) 3(4.699,0)
SPST4_DIP_218-4LPST
  rect 1.27x0.762 smd: 1(-3.81,1.905) 2(-3.81,0.635) 3(-3.81,-0.635) 4(-3.81,-1.905) 5(3.81,-1.905) 6(3.81,-0.635) 7(3.81,0.635) 8(3.81,1.905)
SR1130_3000TR
  rect 3.962x3.962 smd: MINUS(0,0)
  rect 3.175x3.175 smd: PLUS1(-7.874,0) PLUS2(7.874,0)
TANT_0603
  rect 1.1x1 smd: 1(-0.85,0) 2(0.85,0)
TEST_POINT_40-60
  round 1.524 hole 1.016: 1(0,0)
TP_BLACK_5001
  round 1.524 hole 1.016: 1(0,0)
TP_RED_5000
  round 1.524 hole 1.016: 1(0,0)
TP_SMD
  round 1.016 smd: 1(0,0)
TPS74801DRCR
  rect 0.85x0.28 smd: 1(-1.475,1) 2(-1.475,0.5) 3(-1.475,0) 4(-1.475,-0.5) 5(-1.475,-1) 6(1.475,-1) 7(1.475,-0.5) 8(1.475,0) 9(1.475,0.5) 10(1.475,1)
  rect 1.65x3.8 smd: 11(0,0)
TSSOP14
  rect 1.219x0.457 smd: 1(-2.921,1.95) 2(-2.921,1.3) 3(-2.921,0.65) 4(-2.921,0) 5(-2.921,-0.65) 6(-2.921,-1.3) 7(-2.921,-1.95) 8(2.921,-1.95) 9(2.921,-1.3) 10(2.921,-0.65) 11(2.921,0) 12(2.921,0.65) 13(2.921,1.3) 14(2.921,1.95)
UDFN10_SP3010
  rect 0.279x0.686 smd: 1(-0.991,-0.432) 2(-0.483,-0.432) 4(0.483,-0.432) 5(0.991,-0.432) 6(0.991,0.432) 7(0.483,0.432) 9(-0.483,0.432) 10(-0.991,0.432)
  rect 0.406x0.902 smd: 3(0,-0.324) 8(0,0.324)
unnamed
  round 6.35 hole 3.175 unplated: (0,0)
USB3_CMS1811-010010
  rect 0.4x1.35 smd: 1(-1.3,4.125) 2(-0.65,4.125) 3(0,4.125) 4(0.65,4.125) 5(1.3,4.125) 6(5.4,4.125) 7(6.05,4.125) 8(6.7,4.125) 9(7.35,4.125) 10(8,4.125)
  rect 1.8x1.9 smd: 11(-4,1.45) 14(4,1.45) 15(6.5,1.45)
  rect 1.9x1.9 smd: 12(-1.2,1.45) 13(1.2,1.45)
  rect 2.3x1.9 smd: 16(9.1,1.45)
  rect 2.1x1.8 smd: 17(10,3.65) 18(-4.65,3.65)
XTAL_ITTI
  rect 1.245x1.549 smd: 1(0.787,-1.016) 2(0.787,1.016) 3(-0.787,1.016) 4(-0.787,-1.016)

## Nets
5V_DC_INPUT: C119.1 C120.1 J49.2 SW9.1
AVDD: C102.1 C103.1 FB2.1 U1.A7(AVDD)
GND: BT1.MINUS(NEG) C1.2 C2.2 C3.2 C28.2 C29.2 C30.2 C31.2 C32.2 C34.2 C36.2 C37.2 C39.2 C42.2 C44.2 C45.2 C47.2 C49.2 C53.2 C77.2 C78.2 C79.2 C80.2 C81.2 C82.2 C83.2 C84.2 C85.2 C86.2 C87.2 C88.2 C89.2 C90.2 C91.2 C92.2 C102.2 C103.2 C104.2 C105.2 C106.2 C107.2 C108.2 C109.2 C110.2 C111.2 C112.2 C113.2 C114.2 C115.2 C119.2 C120.2 C121.2 C122.2 C123.2 C124.2 C125.2 C126.2 C127.2 C128.2 C129.2 C142.2 C143.2 C158.2 C159.2 C160.2 C161.2 C185.2 C186.2 C197.2 C212.2 C216.1 C217.2 J1.3 J1.39 J1.40 J1.41 J1.42 J1.43 J2.3 J2.39 J2.40 J2.41 J2.42 J2.43 J20.8 J20.9 J20.10 J20.11 J20.12 J20.13 J20.14 J34.7 J34.8 J38.5 J38.10 J38.11 J48.5(GND1) J48.8(GND2) J49.1 J49.3 J50.2 J51.4(GND1) J51.6(GND2) J51.8(GND3) J51.10(GND4) J51.12(GND5) J51.14(GND6) J51.16(GND7) J51.18(GND8) J51.20(GND9) J52.3 J77.121 J77.122 J77.123 J77.124 J77.125 J77.126 J77.127 J77.128 J147.4 L5.2 Q13.2(E) Q14.2(E) Q15.2(E) Q16.2(E) Q17.2(E) R23.1 R34.1 R35.1 R41.1 R42.1 R47.2 R48.2 R58.1 R111.2 R144.1 R238.1 R240.1 R243.1 R247.1 R251.1 R264.2 SW8.A1 SW8.A2 SW25.6 SW25.7 SW25.8 SW40.1 SW40.2 SW40.3 TP11.1 TP12.1 TP14.1 TP16.1 TP17.1 TP18.1 TP19.1 U1.A1(U3VSSQ) U1.A8(VSS12) U1.B7(AVSS) U1.B8(U2PLLVSSQ) U1.B9(U2AFEVSSQ) U1.D8(VSS5) U1.E2(VSS3) U1.G1(VSS1) U1.G11(VSS6) U1.K3(VSS10) U1.K4(VSS8) U1.L1(VSS2) U1.L2(VSS11) U1.L3(VSS9) U1.L6(VSS4) U1.L11(VSS7) U6.18(GND) U7.7(GND) U8.8(GND) U9.3 U9.8 U17.6(GND) U17.11(EPAD) U19.1(GND) U19.2(EN_L) U20.1(GND) U20.2(EN_L) U23.1(GND) U23.2(EN_L) U26.4(VSS) U37.2(GND) U37.3(EN_L) U44.4(GND) U45.2(GND) X2.6(GND) Y3.2 Y3.4
V1P2: C143.1 FB1.2 FB2.2 FB4.2 FB5.2 J134.1 R139.2 R141.2 R300.1 TP43.1 U19.5(OUT1) U19.6(OUT2)
V1P8: C158.1 J134.2 J135.1 J136.1 J144.1 J145.1 J146.1 R241.2 R242.1 R306.1 TP44.1 U20.5(OUT1) U20.6(OUT2)
V2P5: C160.1 J134.3 J136.2 J143.2 J144.2 J145.2 J146.2 R244.2 R245.1 R312.1 TP45.1 U23.5(OUT1) U23.6(OUT2)
V3P3: C28.1 C29.1 C30.1 C31.1 C37.1 C128.1 J134.4 J135.2 J136.3 J143.3 J144.3 J145.3 J146.3 R22.2 R30.2 R31.2 R237.2 R239.2 R308.1 TP10.1 U6.11(VL) U6.19(VCC) U7.14(VCC) U17.9(OUT1) U17.10(OUT2)
V5P0: C3.1 C121.1 C122.1 C123.1 C124.1 C125.1 C126.1 C127.1 C142.1 C159.1 C161.1 D14.1(ANODE) D15.1(ANODE) D16.1(ANODE) D17.1(ANODE) D18.1(ANODE) J20.1 J34.1 J40.1 J143.1 J156.1 R46.1 R310.1 SW9.2 TP9.1 U17.1(IN1) U17.2(IN2) U17.4(BIAS) U17.5(EN) U19.3(IN1) U19.4(IN2) U20.3(IN1) U20.4(IN2) U23.3(IN1) U23.4(IN2) U45.6(VCCB)
V5P0_HDR: J77.113 J77.114 J77.115 J77.116 J156.2
VBAT: BT1.PLUS1(POS1) BT1.PLUS2(POS2) D1.2(ANODE2)
VBUS_HEADER: J53.1 J53.2 SW9.3
VBUS_IN: C47.1 C185.1 J47.1 J53.3 J53.4 L2.2 R190.2 U8.9(OUTA) U37.1(IN)
VDD: C78.1 C79.1 C80.1 C81.1 C82.1 C83.1 C84.1 C85.1 C106.1 C107.1 FB1.1 U1.B10(VDD8) U1.C3(VDD2) U1.E9(VDD4) U1.F11(VDD5) U1.H1(VDD1) U1.J11(VDD7) U1.L5(VDD6) U1.L7(VDD3)
CLKIN: TP15.1(TP) U1.D7(CLKIN)
CLKIN_32: R43.1 U1.D6(CLKIN_32)
CTL0: J1.6 J77.33 R221.2
CTL1: J1.23 J77.51 R222.2
CTL2: J1.25 J77.55 R223.2
CTL3: J1.7 J77.31 R224.2
CTL4: J77.60 J100.1
CTL4_LT: J100.3 U45.3(A)
CTL4_SW: J1.14 J100.2 R225.2
CTL5: J1.13 J77.39 R226.2
CTL6: J1.19 J77.45 R227.2
CTL7: J1.11 J77.37 R228.2
CTL8: J1.21 J77.49 R229.2
CTL9: J1.15 J77.41 R230.2
CTL10: J1.17 J77.43 R231.2
CTL11: J1.16 J77.54 R232.2
CTL12: J1.27 J77.57 R233.2
CVDDQ: C39.1 C112.1 C113.1 J135.3 J135.4 R10.2 R37.2 R38.2 R39.2 R40.1 R63.2 U1.B6(CVDDQ) X2.12(VCC)
DQ0: J1.29 J77.68 R5.2
DQ1: J1.18 J77.74 R205.2
DQ2: J1.20 J77.76 R206.2
DQ3: J1.31 J77.70 R207.2
DQ4: J1.12 J77.50 R208.2
DQ5: J1.28 J77.80 R209.2
DQ6: J1.8 J77.32 R210.2
DQ7: J1.10 J77.42 R211.2
DQ8: J1.24 J77.66 R212.2
DQ9: J1.36 J77.89 R213.2
DQ10: J1.33 J77.61 R214.2
DQ11: J1.30 J77.79 R215.2
DQ12: J1.35 J77.71 R216.2
DQ13: J1.32 J77.81 R217.2
DQ14: J1.37 J77.65 R218.2
DQ15: J1.34 J77.83 R219.2
DQ16: J2.11 J77.56 R6.2
DQ17: J2.27 J77.85 R12.2
DQ18: J2.19 J77.73 R13.2
DQ19: J2.29 J77.87 R14.2
DQ20: J2.23 J77.77 R15.2
DQ21: J2.21 J77.75 R16.2
DQ22: J2.17 J77.69 R17.2
DQ23: J2.25 J77.67 R18.2
DQ24: J2.37 J77.78 R20.2
DQ25: J2.35 J77.72 R21.2
DQ26: J2.15 J77.63 R44.2
DQ27: J2.13 J77.58 R45.2
DQ28: J2.7 J77.38 R49.2
DQ29: J2.31 J77.62 R50.2
DQ30: J2.9 J77.40 R56.2
DQ31: J2.33 J77.64 R57.2
FAULTA_L: R46.2 TP28.1(TP) U8.10(FAULTA_L)
FLAG: R190.1 U37.4(FLAG)
FSLC0: R37.1 R41.2 U1.B2(FSLC0)
FSLC1: R38.1 R42.2 U1.B4(FSLC1)
FSLC2: R39.1 R58.2 U1.E6(FSLC2)
GPIO45: J2.20 TP13.1(TP) U1.F2(GPIO45)
I2C_CHARGER_DETECT: TP31.1(TP) U1.D11(I2C-GPIO60_CHARGER-DETECT)
I2C_SCL_EEPROM: J42.1 J147.2 U44.6(SCL)
I2C_SCL_FX3: J2.34 J42.2 R176.1 U1.D9(I2C-GPIO58_SCL)
I2C_SCL_PPORT: J2.26 J42.3 J77.88
I2C_SDA_EEPROM: J45.1 J147.3 U44.5(SDA)
I2C_SDA_FX3: J2.32 J45.2 R186.1 U1.D10(I2C-GPIO59_SDA)
I2C_SDA_PPORT: J2.24 J45.3 J77.86
I2S-MCLK: J2.6 J20.7 J77.90 R261.2
I2S_CLK: J2.5 J20.4 J77.95 R254.2
I2S_SD: J2.14 J20.5 J77.93 R255.2
I2S_WP: J2.18 J20.6 J77.91 R256.2
INT_N_CTL15: J1.22 J77.52 R170.1 U1.L8(INT_N_CTL15)
N_SRST: J51.15(N_SRST) R51.1
OTG_ID: J48.4(ID) J50.1 U1.C9(OTG_ID)
PCLK: J1.5 J77.44 R220.2
PMODE0_CON: J77.36 J96.1
PMODE1_CON: J77.46 J97.1
PMODE2_CON: J77.30 J98.1
PMODE_0: J96.2 R234.2
PMODE_0_DIP: J96.3 R7.1 SW25.1
PMODE_1: J97.2 R235.2
PMODE_1_DIP: J97.3 R8.1 SW25.2
PMODE_2: J98.2 R236.2
PMODE_2_DIP: J98.3 R19.1 SW25.3
REG_VBATT: D1.1(ANODE1) J74.2 J143.4 J143.5 J143.6
RESET_N: J1.38 J72.2 R10.1 U1.C5(RESET_N)
RESET_N_CON: J72.3 J77.59
RESET_SWITCH: C1.1 J72.1 R63.1 SW8.B1 SW8.B2
RS232_CTS_OUT: J38.7 R27.1
RS232_RTS_IN: J38.8 R33.1
RS232_RX_IN: J38.3 R29.1
RS232_TX_OUT: J38.2 R25.1
RTCK: J51.11(RTCK) J52.2
SPI-MISO_UART-TX: J2.10 J103.2 R259.2
SPI-MOSI_UART-RX: J2.8 J104.2 R260.2
SPI-SCK_UART-RTS: J2.16 J101.2 R257.2
SPI-SSN_UART-CTS: J2.12 J102.2 R258.2
SPI_CLK: J34.3 J101.3 R61.1
SPI_CLK_FLASH: R61.2 R247.2 U26.6(C)
SPI_HOLD#_FLASH: R248.2 U26.7(H\O\L\D\)
SPI_MISO: J34.6 J103.3 R60.1
SPI_MISO_FLASH: R60.2 R246.2 U26.2(Q)
SPI_MOSI: J34.4 J104.3 R59.1
SPI_MOSI_FLASH: R59.2 R252.2 U26.5(D)
SPI_SSN: J34.5 J102.3 R62.1
SPI_SSN_FLASH: R62.2 R249.2 U26.1(S\)
SPI_WP#_FLASH: R250.2 R251.2 U26.3(W\/VPP)
SS_DM: J48.2(D-) U1.A10(DM)
SS_DP: J48.3(D+) U1.A9(DP)
SS_RX_M: J48.10(MICRO_SSRX+) U1.A3(SSRXM) U9.5 U9.6
SS_RX_P: J48.9(MICRO_SSRX-) U1.A4(SSRXP) U9.4 U9.7
SS_TX_M: C46.2 J48.6(MICRO_SSTX-) U9.1 U9.10
SS_TX_P: C43.2 J48.7(MICRO_SSTX+) U9.2 U9.9
TCK: J51.9(TCK) J52.1 R52.1 U1.F6(TCK)
TDI: J51.5(TDI) R54.1 U1.E7(TDI)
TDO: J51.13(TDO) U1.C10(TDO)
TMS: J51.7(TMS) R53.1 U1.E8(TMS)
TRST_N: J51.3(N_TRST) R55.1 U1.B11(TRST_N)
U3RX_VDDQ: C91.1 C92.1 FB4.1 U1.A2(U3RXVDDQ)
U3TX_VDDQ: C104.1 C105.1 FB5.1 U1.B5(U3TXVDDQ)
UART_CTS: J102.1 U7.3(IO VL2)
UART_CTS_LT: R26.2 U7.12(IO VCC2)
UART_FORCE_OFF: R31.1 R35.2 U6.20(FORCEOFF#)
UART_FORCE_ON: R30.1 R34.2 U6.14(FORCEON)
UART_READY: R22.1 R23.2 U6.1(READY)
UART_RTS: J101.1 U7.2(IO VL1)
UART_RTS_LT: R32.2 U7.13(IO VCC1)
UART_RX: J104.1 U7.5(IO VL4)
UART_RX_LT: R28.2 U7.10(IO VCC4)
UART_TX: J103.1 U7.4(IO VL3)
UART_TX_LT: R24.2 U7.11(IO VCC3)
USB3_VBUS: C186.1 U1.E11(VBUS) U37.5(OUT)
USB_DRV_VBUS: R264.1 TP46.1(TP) U8.1(ONA) U45.4(B)
VIO1: C2.1 C86.1 C87.1 C88.1 J125.1 J136.4 J136.5 J136.6 R7.2 R8.2 R11.2 R19.2 R170.2 U1.H11(VIO1_2) U1.L9(VIO1_1) U45.1(VCCA)
VIO1_HDR: J77.1 J77.2 J77.3 J77.4 J77.117 J77.118 J77.119 J77.120 J125.2
VIO2: C108.1 C109.1 J144.4 J144.5 J144.6 U1.F1(VIO2)
VIO3: C110.1 C111.1 J20.2 J145.4 J145.5 J145.6 U1.E3(VIO3)
VIO4: C36.1 C77.1 C114.1 C115.1 J20.3 J34.2 J146.4 J146.5 J146.6 R36.2 R246.1 R248.1 R249.1 R250.1 R252.1 U1.B1(VIO4) U7.1(VL) U26.8(VCC)
VIO5: C89.1 C90.1 C197.1 C212.1 J51.1(VT_REF) J51.2(V_SUPPLY) J134.5 J134.6 J134.7 J134.8 J147.1 R51.2 R52.2 R53.2 R54.2 R55.2 R110.1 R176.2 R186.2 R262.1 R263.1 U1.C11(VIO5) U44.8(VCC)
XTALIN: C216.2 U1.C6(XTALIN) Y3.1
XTALOUT: C217.1 U1.C7(XTALOUT) Y3.3
N13394127: C53.1 D1.3(CATHODE) J74.1 U1.E10(VBAT)
N13841009: R36.1 U7.8(/TS)
N13880067: R29.2 U6.16(R1_IN)
N13882405: R25.2 U6.17(T1_OUT)
N13882880: R27.2 U6.9(R2_IN)
N13883880: R33.2 U6.8(T2_OUT)
N13897864: R32.1 U6.12(T2_IN)
N13897866: R28.1 U6.15(R1_OUT)
N13897868: R26.1 U6.10(R2_OUT)
N13897870: R24.1 U6.13(T1_IN)
N13929197: C33.1 U6.2(C1+)
N13930227: C33.2 U6.4(C1-)
N13931322: C35.1 U6.5(C2+)
N13931334: C35.2 U6.6(C2-)
N13944533: C32.1 U6.3(V+)
N13945074: C34.1 U6.7(V-)
N16663499: R43.2 X2.7(OUT)
N17004628: C42.1 F1.2 U8.2(INA) U8.3(IN) U8.4(INB)
N17006752: F1.1 L1.2
N17006789: J40.2 L1.1
N17020961: C44.1 C45.1 J47.2
N17052408: C43.1 U1.A5(SSTXP)
N17056303: C46.1 U1.A6(SSTXM)
N17073855: C49.1 J48.11(SHIELD1) J48.12(SHIELD2) J48.13(SHIELD3) J48.14(SHIELD4) J48.15(SHIELD5) J48.16(SHIELD6) J48.17(SHIELD7) J48.18(SHIELD8) L5.1
N17441604: R47.1 U1.B3(R_USB3)
N17441606: R48.1 U1.C8(R_USB2)
N17676874: R40.2 X2.1(VIO)
N20153874: J48.1(VBUS) L2.1
N20184217: R5.1 U1.F10(DQ0)
N20186132: R205.1 U1.F9(DQ1)
N20187007: R206.1 U1.F7(DQ2)
N20187884: R207.1 U1.G10(DQ3)
N20188787: R208.1 U1.G9(DQ4)
N20188789: R209.1 U1.F8(DQ5)
N20188799: R210.1 U1.H10(DQ6)
N20188809: R211.1 U1.H9(DQ7)
N20189728: R212.1 U1.J10(DQ8)
N20189730: R213.1 U1.J9(DQ9)
N20189740: R214.1 U1.K11(DQ10)
N20189750: R215.1 U1.L10(DQ11)
N20190677: R216.1 U1.K10(DQ12)
N20190679: R217.1 U1.K9(DQ13)
N20190689: R218.1 U1.J8(DQ14)
N20190699: R219.1 U1.G8(DQ15)
N20191634: R220.1 U1.J6(PCLK)
N20191636: R221.1 U1.K8(CTL0)
N20191646: R222.1 U1.K7(CTL1)
N20191656: R223.1 U1.J7(CTL2)
N20192599: R224.1 U1.H7(CTL3)
N20192601: R225.1 U1.G7(CTL4)
N20192611: R226.1 U1.G6(CTL5)
N20192621: R227.1 U1.K6(CTL6)
N20193572: R228.1 U1.H8(CTL7)
N20193574: R229.1 U1.G5(CTL8)
N20193584: R230.1 U1.H6(CTL9)
N20193594: R231.1 U1.K5(CTL10)
N20194553: R232.1 U1.J5(CTL11)
N20195482: R233.1 U1.H5(CTL12)
N20198119: R234.1 U1.G4(PMODE0)
N20199051: R235.1 U1.H4(PMODE1)
N20199985: R236.1 U1.L4(PMODE2)
N21712030: Q13.3(C) R301.1
N21712032: Q13.1(B) R300.2
N21712149: D14.2(CATHODE) R301.2
N21712617: Q14.3(C) R302.1
N21712619: Q14.1(B) R306.2
N21712675: D18.2(CATHODE) R302.2
N21838652: R254.1 U1.D1(I2S-CLK)
N21838662: R255.1 U1.D2(I2S-SD)
N21838672: R256.1 U1.D3(I2S-WS)
N21838834: R261.1 U1.C4(I2S-MCLK)
N21839162: R257.1 U1.D4(UART-RTS_SPI-SCK)
N21839172: R258.1 U1.C1(UART-CTS_SPI-SSN)
N21839182: R259.1 U1.C2(UART-TX_SPI-MISO)
N21839192: R260.1 U1.D5(UART-RX_SPI-MOSI)
N21886398: R11.1 U45.5(OE)
N21902204: R6.1 U1.K2(DQ16)
N21902237: R12.1 U1.J4(DQ17)
N21902264: R13.1 U1.K1(DQ18)
N21902291: R14.1 U1.J2(DQ19)
N21902318: R15.1 U1.J3(DQ20)
N21902345: R16.1 U1.J1(DQ21)
N21902372: R17.1 U1.H2(DQ22)
N21902399: R18.1 U1.H3(DQ23)
N21902426: R20.1 U1.F4(DQ24)
N21902453: R21.1 U1.G2(DQ25)
N21902480: R44.1 U1.G3(DQ26)
N21902507: R45.1 U1.F3(DQ27)
N21902708: R49.1 U1.F5(DQ28)
N21902721: R50.1 U1.E1(DQ29)
N21902734: R56.1 U1.E5(DQ30)
N21902747: R57.1 U1.E4(DQ31)
N21904014: R237.1 U17.3(PG)
N21904020: R238.2 R239.1 U17.8(FB)
N21904073: C129.1 U17.7(SS)
N21905805: R141.1 R144.2 U19.7(FB)
N21905847: R139.1 U19.8(PG)
N21905950: R240.2 R242.2 U20.7(FB)
N21905997: R241.1 U20.8(PG)
N21906513: R243.2 R245.2 U23.7(FB)
N21906562: R244.1 U23.8(PG)
N21921971: R110.2 SW40.6 U44.3(A2)
N21921973: R263.2 SW40.7 U44.2(A1)
N21921975: R262.2 SW40.8 U44.1(A0)
N21922075: R111.1 U44.7(WP)
N22050803: Q15.3(C) R307.1
N22050805: Q15.1(B) R308.2
N22050813: D15.2(CATHODE) R307.2
N22050947: Q16.3(C) R309.1
N22050949: Q16.1(B) R310.2
N22050957: D16.2(CATHODE) R309.2
N22051184: Q17.3(C) R311.1
N22051186: Q17.1(B) R312.2
N22051194: D17.2(CATHODE) R311.2

Pads without a net: J1 1 2 4 9 26; J2 1 2 4 22 28 30 36 38; J38 1 4 6 9; J51 17 19; J77 5 6 7 8 9 10 11 12 13 14 15 16 17 18 19 20 21 22 23 24 25 26 27 28 29 34 35 47 48 53 82 84 92 94 96 97 98 99 100 101 102 103 104 105 106 107 108 109 110 111 112; SW25 4 5; SW40 4 5; U1 A11; U7 6 9; U8 5 6 7; X2 2 3 4 5 8 9 10 11

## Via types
v1: diameter 0.406, hole 0.203, TOP to BOTTOM, 287 vias
v2: diameter 0.356, hole 0.203, TOP to BOTTOM, 128 vias
v3: diameter 0.508, hole 0.254, TOP to BOTTOM, 236 vias
v4: diameter 0.61, hole 0.305, TOP to BOTTOM, 47 vias
v5: diameter 0.6, hole 0.3, TOP to BOTTOM, 5 vias

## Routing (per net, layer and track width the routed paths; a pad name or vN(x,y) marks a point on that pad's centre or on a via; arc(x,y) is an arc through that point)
5V_DC_INPUT:
  vias: v3(83.06,10.47) v3(84.52,10.47)
AVDD: length 0.9
  TOP w0.254: U1.A7 68.64,61.75 68.87,61.75 68.99,61.63 v2(69.36,61.26)
  vias: v2(69.53,60.75) v3(74.86,66.97) v3(75.6,66.96) v3(76.26,67.08)
GND: length 159
  TOP w0.127: C122.2 65.53,9.25 v3(65.53,8)
  TOP w0.254: U8.8 87.39,34.42 87.62,34.19 87.62,34.18 87.88,33.91 ; v2(68.07,59.92) U1.B9 ; v2(63.45,58.05) 63.84,58.45 U1.G11 ; J48.5 91.56,58.41 91.44,58.53 v1(91.43,58.53) ; v3(60.22,8.99) 60.2,8.99 59.8,8.59 U17.6 ; v2(60.24,65.35) 60.45,65.14 U1.L3 ; U1.D8 v2(66.64,60.55) ; U1.E2 65.57,65.88 65.57,65.88 v2(65.84,66.15) ; v3(79.49,56.9) 79.47,56.88 X2.6 ; v2(60.01,62.16) 60.01,62.16 60.41,62.55 U1.L6 ; U1.A1 68.86,66.77 68.86,66.77 v2(69.04,66.95) ; U1.B7 68,61.91 68,61.91 v2(68.24,62.15) ; U1.L11 60.52,58.67 v2(60.2,58.67) ; U1.L2 v2(60.24,66.15) ; v2(60.24,66.95) U1.L1
  TOP w0.305: U1.K4 v2(61.04,64.55) ; U1.K3 v2(61.04,65.35) ; U1.A8 v2(68.24,61.35) 67.84,60.95 U1.B8 ; v2(63.44,66.95) 63.84,66.55 U1.G1
  TOP w0.381: v3(11.81,79.88) J77.122 v3(11.81,74.68) ; v3(11.81,68.39) J77.123 v3(11.81,73.53) ; J48.8 91.39,63.81 v2(91.31,63.73) ; v3(11.81,53.53) J77.127 v3(11.81,48.29) ; v3(11.83,60.67) 11.81,60.69 J77.125 11.81,63.77 v3(11.87,63.84) ; 87.88,33.91 88.61,33.19 C47.2 ; J1.3 25.33,67.8 25.64,68.11 25.64,68.13 v3(25.75,68.23) ; v2(88.23,63.69) U9.8 U9.3 v2(90.26,63.69) ; U7.7 60.05,88.98 59.97,88.9 59.96,88.9 v3(59.9,88.84) ; J2.3 v3(42.5,79.01) ; v3(11.82,59.88) 11.81,59.87 J77.126 v3(11.81,54.64) ; v3(11.81,67.76) 11.81,67.76 J77.124 v3(11.81,64.39) ; 11.81,82.15 v3(11.81,80.52) ; J77.128 v3(11.81,47.65)
  TOP w0.432: v4(71.75,92.71) 72.11,92.35 U6.18
  TOP w0.508: v3(79.47,70.33) 79.95,70.81 Y3.2 ; v4(88.73,32.21) 88.9,32.38 C47.2 ; v4(70.92,92.14) 70.91,92.14 70.36,91.59 R35.1 ; C3.2 v3(24.07,100.13) ; v3(81.46,37.93) R264.2 ; v3(39.43,13.79) 39.3,13.66 R243.1 ; C129.2 v3(61.04,11.81) ; R41.1 v3(68.71,75.82) ; U37.3 v3(70.13,30.02) ; U26.4 v3(61.98,98.81) ; U37.2 71.75,31.57 C185.2 v3(71.3,31.62) ; C217.2 v3(82.77,68.03) ; R238.1 v3(60.02,11.81) ; C1.2 v3(11.05,107.7) ; C127.2 v3(61.09,3.81) ; R58.1 v3(73.03,75.82) ; R240.1 v3(28.65,13.79) ; R42.1 v3(70.74,75.82) ; 74.51,53.73 v3(75.64,52.6) 78.22,52.6 78.22,52.6 v3(78.91,52.6) 79.59,52.6 80.13,53.14 v3(80.13,55.36) 80.13,56.25 v3(79.49,56.9) 78.56,57.83 v3(77.5,57.83) 75.24,57.83 74.51,57.09 v3(74.51,55.42) 74.51,53.73
  TOP w0.635: 77.91,66.75 82.19,66.75 82.77,67.33 v3(82.77,68.03) 83.42,68.67 v3(83.42,71.29) 83.42,74.43 82.29,75.56 81.55,75.56 81.53,75.58 ; 77.91,66.75 76.83,67.82 ; 77.91,66.75 77.91,66.77 v3(77.21,67.47) 76.85,67.82 76.83,67.82 ; C2.2 v3(17,100.13) ; v3(81.5,75.61) 80.54,76.57 v1(77.51,76.57) 76.42,76.57 75.94,76.1 75.94,72.54 v3(76.38,72.11) 76.74,71.74 76.74,67.91 76.83,67.82 ; U45.2 v3(20.22,100.2) ; R144.1 v3(35.22,45.47)
  TOP w0.762: v3(42.86,46.61) Q13.2
  TOP w1.016: v3(81.5,75.61) 81.53,75.58 Y3.4 ; C216.1 77.44,76.17 77.51,76.24 v1(77.51,76.57)
  BOTTOM w0.127: v3(71.63,21.51) C124.2
  BOTTOM w0.305: v2(68.24,61.35) 68.49,61.6 C102.2 68.49,61.9 v2(68.24,62.15)
  BOTTOM w0.381: v2(65.04,63.75) 65.09,63.79 65.29,64 C110.2 ; C79.2 63.68,58.36 63.68,58.28 63.45,58.05 v2(63.45,58.05) ; v2(68.07,59.92) 68.35,59.64 C107.2 C106.2 ; v2(69.04,66.95) 69.05,66.95 69.56,66.95 69.79,66.72 R47.2 ; C88.2 59.91,58.96 v2(60.2,58.67) ; C78.2 60.16,62.31 v2(60.01,62.16) ; C81.2 66.83,65.16 66.2,65.79 66.2,65.79 v2(65.84,66.15) 65.62,66.37 C111.2 ; v3(59.56,92.12) 59.56,92.11 59.79,91.88 C36.2 ; C37.2 v3(65.68,91.88) ; C82.2 65.11,62.08 v2(65.04,62.15) 65.74,62.84 C104.2 ; v2(61.04,64.55) 60.71,64.21 C84.2
  BOTTOM w0.508: 65.28,56.77 65.34,56.83 C53.2 ; Q17.2 44.59,3.82 v3(43.94,3.17) ; C39.2 v3(79.49,56.9) ; R23.1 v4(76.79,91.89) ; Q16.2 78.93,1.46 v3(78.99,1.52) ; v4(77.98,93.47) 78.81,93.47 C32.2 ; R251.1 61.54,98.37 v3(61.98,98.81) ; C77.2 v1(59.51,110.81) ; C34.2 v4(77.98,95.7) ; v3(51.05,2.29) 51.42,1.92 Q15.2 ; R247.1 v1(60.71,111.63)
  BOTTOM w0.635: R111.2 v3(33.33,115.42) ; C212.2 v3(27.94,115.4) ; R48.2 70.23,58.74 70.65,58.33 v1(71.17,58.33) ; C197.2 v3(29.08,115.36)
  vias: v1(61.95,55.61) v1(62.49,55.89) v1(62.66,55.33) v1(63.22,55.84) v1(65.58,52.51) v1(66.92,52.51) v1(68.29,56.64) v1(90.88,59.12) v1(91.4,59.13) v2(68.62,68.53) v2(69.46,68.3) v2(71.13,66.78) v2(73.15,61.21) v2(73.15,60.58) v2(76.35,65.61) v2(76.78,66.12) v3(15.97,117.79) v3(17.31,117.76) v3(18.61,117.79) v3(21.84,9.7) v3(21.82,8.66) v3(23.55,6.86) v3(25.48,4.45) v3(26.77,4.45) v3(27.33,2.24) v3(28.09,2.26) v3(32.43,94.39) v3(33.43,9.45) v3(33.4,8) v3(33.6,94.37) v3(34.44,6.58) v3(35.41,94.52) v3(36.37,4.17) v3(37.16,41.29) v3(37.16,40.54) v3(37.17,39.52) v3(37.67,4.17) v3(38.23,1.96) v3(38.35,41.27) v3(38.35,40.51) v3(38.35,39.5) v3(38.99,1.98) v3(55.88,2.29) v3(56.26,3.81) v3(56.39,1.14) v3(57.28,1.14) v3(64.59,9.98) v3(64.67,8.43) v3(64.67,7.52) v3(68.96,3.68) v3(69.09,2.54) v3(69.55,23.57) v3(69.49,22.23) v3(69.46,19.94) v3(70.54,19.91) v3(70.97,24.22) v3(72.59,24.22) v3(73.04,20.28) v3(73.41,3.81) v3(73.53,2.79) v3(82.04,3.17) v3(82.04,2.29) v3(84.94,27.97) v3(84.99,26.64) v3(85.85,3.17) v3(85.85,2.29) v3(86.02,29.41) v3(86.06,25.75) v3(87.16,25.72) v3(87.32,29.39) v4(36.41,36.72) v4(36.41,35.65) v4(37.55,36.63) v4(42.14,36.69) v4(42.5,35.13) v4(43.94,35.17) v4(72.99,99.19) v4(73.87,99.17) v4(74.99,92.73) v4(91.44,47.7) v4(91.44,46.56) v4(92.46,48.84) v4(92.58,45.79) v5(58.05,7.23) v5(58.05,6.23) v5(58.8,6.73) v5(59.55,7.23) v5(59.55,6.23)
V1P2: length 0.6
  TOP w0.508: R139.2 34.05,44.02 v3(34.05,44.63) 34.05,44.64
  vias: v3(43.31,45.47) v3(43.31,44.58) v3(44.32,45.47) v3(44.32,44.58) v3(45.34,45.47) v3(45.34,44.58) v3(46.23,45.47) v3(46.23,44.58)
V1P8: length 1.2
  TOP w0.508: R242.1 v3(27.05,14.37) ; R241.2 25.91,14.37
  vias: v3(25.91,14.37) v3(30.61,12.7) v3(30.61,11.81) v3(30.61,10.92) v3(31.5,12.7) v3(31.5,11.81) v3(31.5,10.92)
V2P5: length 2.7
  TOP w0.508: R245.1 v3(37.72,14.48) ; R244.2 v3(36.7,14.48)
  BOTTOM w0.508: v3(44.96,2.03) R312.1
  vias: v3(42.94,9.91) v3(42.94,8.89) v3(42.98,10.92) v3(43.94,10.92) v3(43.94,9.96) v3(43.94,8.89)
V3P3: length 3.8
  TOP w0.381: U7.14 v3(65.94,92.88)
  TOP w0.508: R31.2 72.14,91.38
  BOTTOM w0.381: v3(65.94,92.88) 66.32,92.88 C37.1
  BOTTOM w0.508: R30.2 v4(75.95,93.09) ; R237.2 v3(56.77,5.21)
  vias: v3(54.75,9.09) v3(54.75,8.08) v3(54.79,10.11) v3(55.75,10.11) v3(55.75,9.14) v3(55.75,8.08) v4(71.97,97.77) v4(72.09,96.96) v4(72.35,91.5) v4(74.58,91.69) v4(75.5,91.82)
V5P0: length 5.4
  TOP w0.508: v3(76.45,3.43) 76.96,2.92 R310.1 ; D15.1 v1(54.74,2.29) ; v3(84.64,37.93) R46.1 ; D17.1 44.32,4.36 v1(44.32,5.33)
  TOP w0.762: D18.1 v3(35.9,1.38) ; D14.1 v3(45.12,46.61)
  vias: v3(21.76,101.76) v3(22.65,101.73) v3(28.96,4.57) v3(29.84,4.57) v3(30.48,3.53) v3(30.51,2.69) v3(41.47,6.31) v3(41.49,5.28) v3(41.45,3.45) v3(41.48,2.62) v3(58.22,3.03) v3(58.45,3.81) v3(59.51,2.36) v3(59.59,3.21) v3(59.56,1.68) v3(68.58,15.88) v3(68.58,14.73) v3(69.34,13.97) v3(69.47,11.43) v3(70.23,11.18) v3(70.87,13.84) v3(70.99,11.43) v3(71.5,14.99) v3(71.88,10.79) v3(72.45,15.05) v4(39.37,36.58) v4(40.27,35.64) v4(40.64,36.83)
V5P0_HDR: length 8.6
  TOP w0.254: v3(6.85,48.4) 6.88,48.4 6.92,48.36 7.01,48.36 7.04,48.33 J77.113 ; J77.115 v3(7.24,47.83) ; v3(16.71,47.77) 16.65,47.83 J77.116 ; v3(17.42,48.29) 17.37,48.33 J77.114
VBAT:
  vias: v3(31.29,33.03) v3(32.07,32.63) v3(32.16,33.45) v3(32.83,32.95)
VBUS_IN: length 10.7
  TOP w0.508: v2(72.69,32.46) 72.71,32.44 C185.1 72.71,31.37 72.69,31.35 ; v2(72.69,32.46) 72.69,31.35 ; v2(72.69,32.46) 72.29,32.86 70.79,32.86 68.96,31.04 R190.2 ; 72.69,31.35 U37.1
  vias: v2(73.48,32.42) v2(88.58,35.84) v2(89.19,35.84)
VDD: length 8.4
  TOP w0.254: U1.H1 63.04,66.55 63.04,66.55 v2(62.64,66.95) ; U1.L7 60.41,61.75 v2(60.02,61.35) ; v2(64.26,57.9) 64.41,58.4 U1.F11 ; U1.E9 65.31,60.28 v2(65.04,60.55) ; v2(59.88,63.39) 59.92,63.35 U1.L5 ; v2(67.44,65.35) 67.26,65.16 67.25,65.16 U1.C3 ; U1.B10 v2(68.03,59.16) ; U1.J11 v2(61.84,58.15)
  BOTTOM w0.305: v2(67.44,65.35) 67.49,65.3 C81.1
  BOTTOM w0.381: 62.62,67.09 62.88,67.35 C80.1 ; v2(59.88,63.39) 60.04,63.55 C84.1 ; v2(68.03,59.16) 68.21,58.98 C107.1 ; v2(60.02,61.35) 60.31,61.65 C78.1 ; v2(65.04,60.55) 65.11,60.62 C82.1 ; C79.1 64.4,58.01 64.29,57.9 v2(64.26,57.9)
  vias: v3(58.29,67.46) v3(59.26,67.27) v3(59.69,68.71) v3(59.95,67.65)
CLKIN: length 10.5
  TOP w0.203: U1.D7 v2(66.64,61.35)
  TOP w0.508: v1(66.25,52.53) 66.25,51.74 TP15.1
  SIG1#3 w0.127: v1(66.25,52.53) 66.25,52.53 66.25,60.95 arc(66.36,61.23) v2(66.64,61.35)
CLKIN_32: length 10
  TOP w0.203: v2(66.64,62.15) 66.4,62.39 U1.D6
  SIG1#3 w0.127: v1(72.64,56.9) 72.22,56.9 arc(71.99,56.94) 71.79,57.07 68.11,60.75 arc(67.9,60.9) 67.65,60.94 67.31,60.94 arc(67.22,60.96) 67.14,61.01 arc(67.07,61.12) 67.05,61.25 67.05,61.75 arc(66.93,62.03) v2(66.64,62.15)
  BOTTOM w0.483: R43.1 v1(72.64,56.9)
CTL0: length 76
  TOP w0.254: J77.33 10.77,73.33 10.83,73.4 v1(10.84,73.4)
  TOP w0.381: v1(32.87,67.71) 32.74,67.58 32.74,67.56 32.34,67.16 J1.6
  SIG1#3 w0.127: v1(53.89,64.39) 54.89,65.39 54.89,68.19 54.59,68.5 53.89,68.5 53.18,67.78 53.18,67.78 53.14,67.74 51.9,67.74 51.73,67.91 50.68,67.91 50.68,67.92 49.68,67.92 49.68,67.91 49.67,67.91 48.95,67.2 48.95,67.06 48.13,66.24 47.88,65.99 47.03,65.14 47.02,65.14 45.57,63.69 36.87,63.69 32.87,67.69 v1(32.87,67.71) 32.86,67.71 30.62,69.95 30.62,74.68 30.6,74.72 30.54,74.87 22.85,82.56 22.82,82.56 22.41,82.97 11.63,82.97 9.69,81.04 9.69,76.69 10.84,75.54 v1(10.84,73.4)
  BOTTOM w0.483: R221.2 54.4,64.77 54.02,64.39 v1(53.89,64.39)
